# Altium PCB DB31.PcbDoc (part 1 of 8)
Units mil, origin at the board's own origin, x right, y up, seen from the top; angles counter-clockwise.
Board outline 3236.22 x 4456.69 mil, 8 copper layers (Top Layer, MidLayer1, MidLayer2, GND-Layer5, MidLayer3, VCC, MidLayer4, Bottom Layer), stack 61.8 mil thick; 226 components, 469 nets, 1815 pads, 1562 vias.
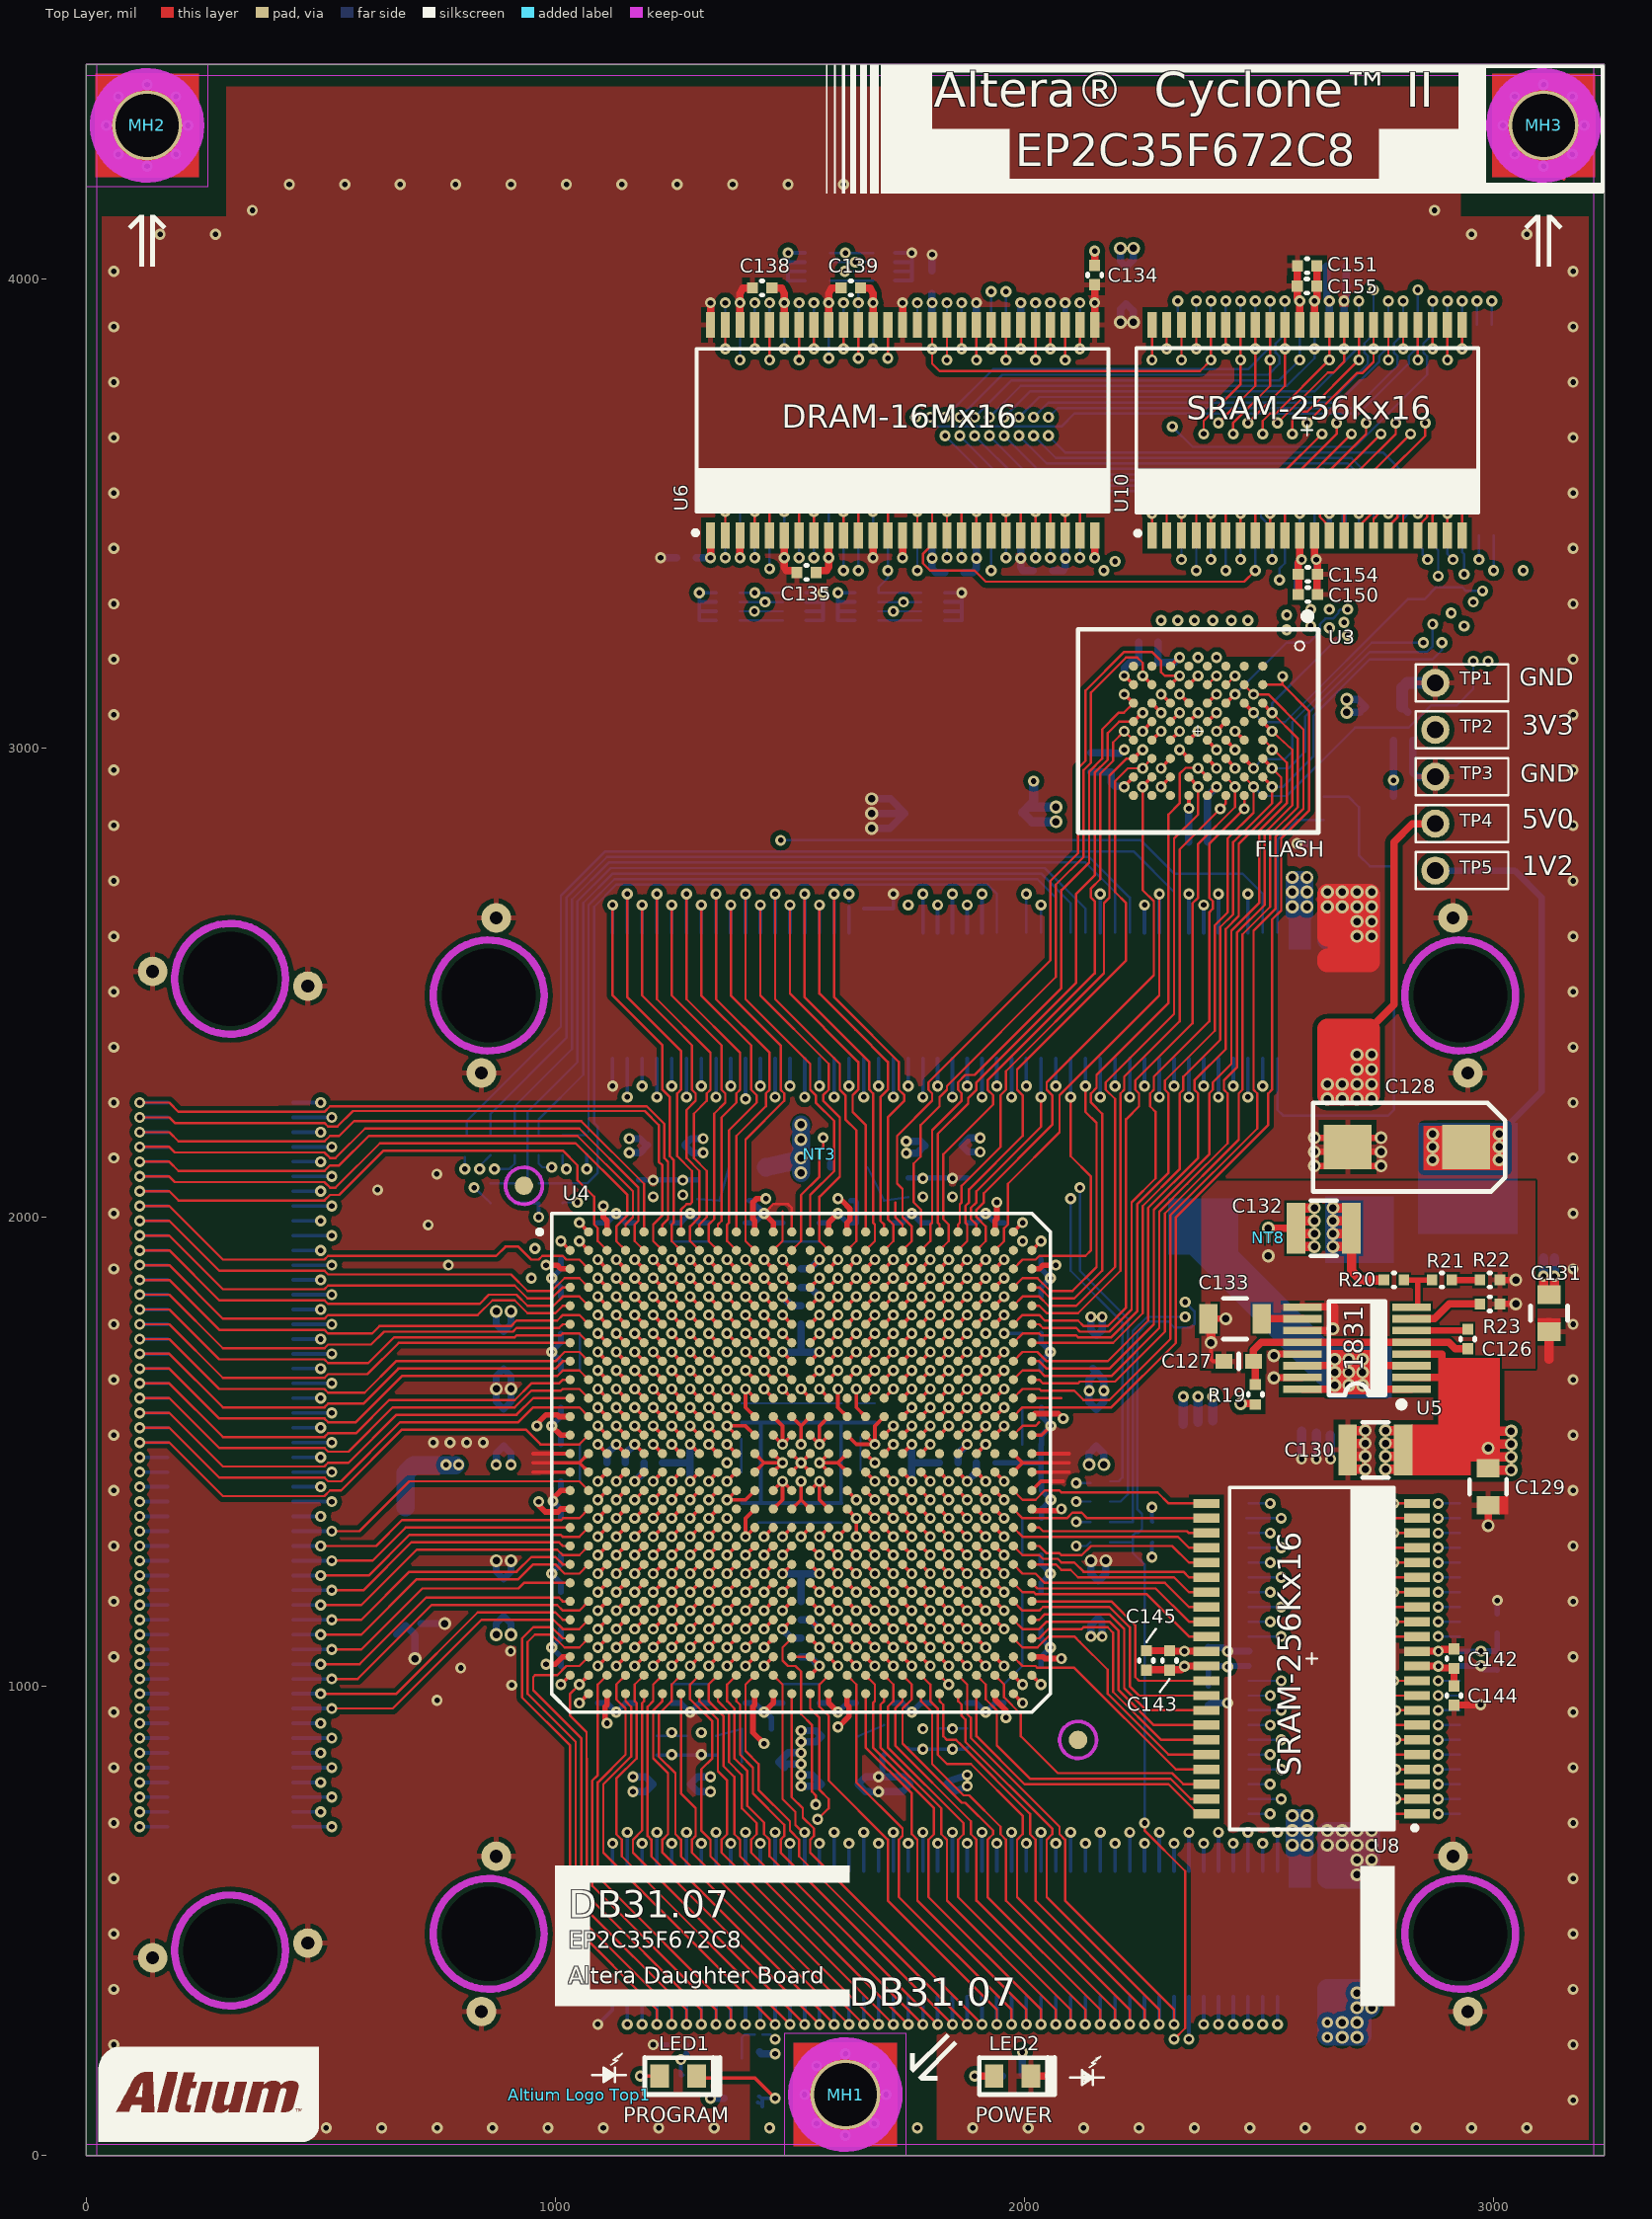
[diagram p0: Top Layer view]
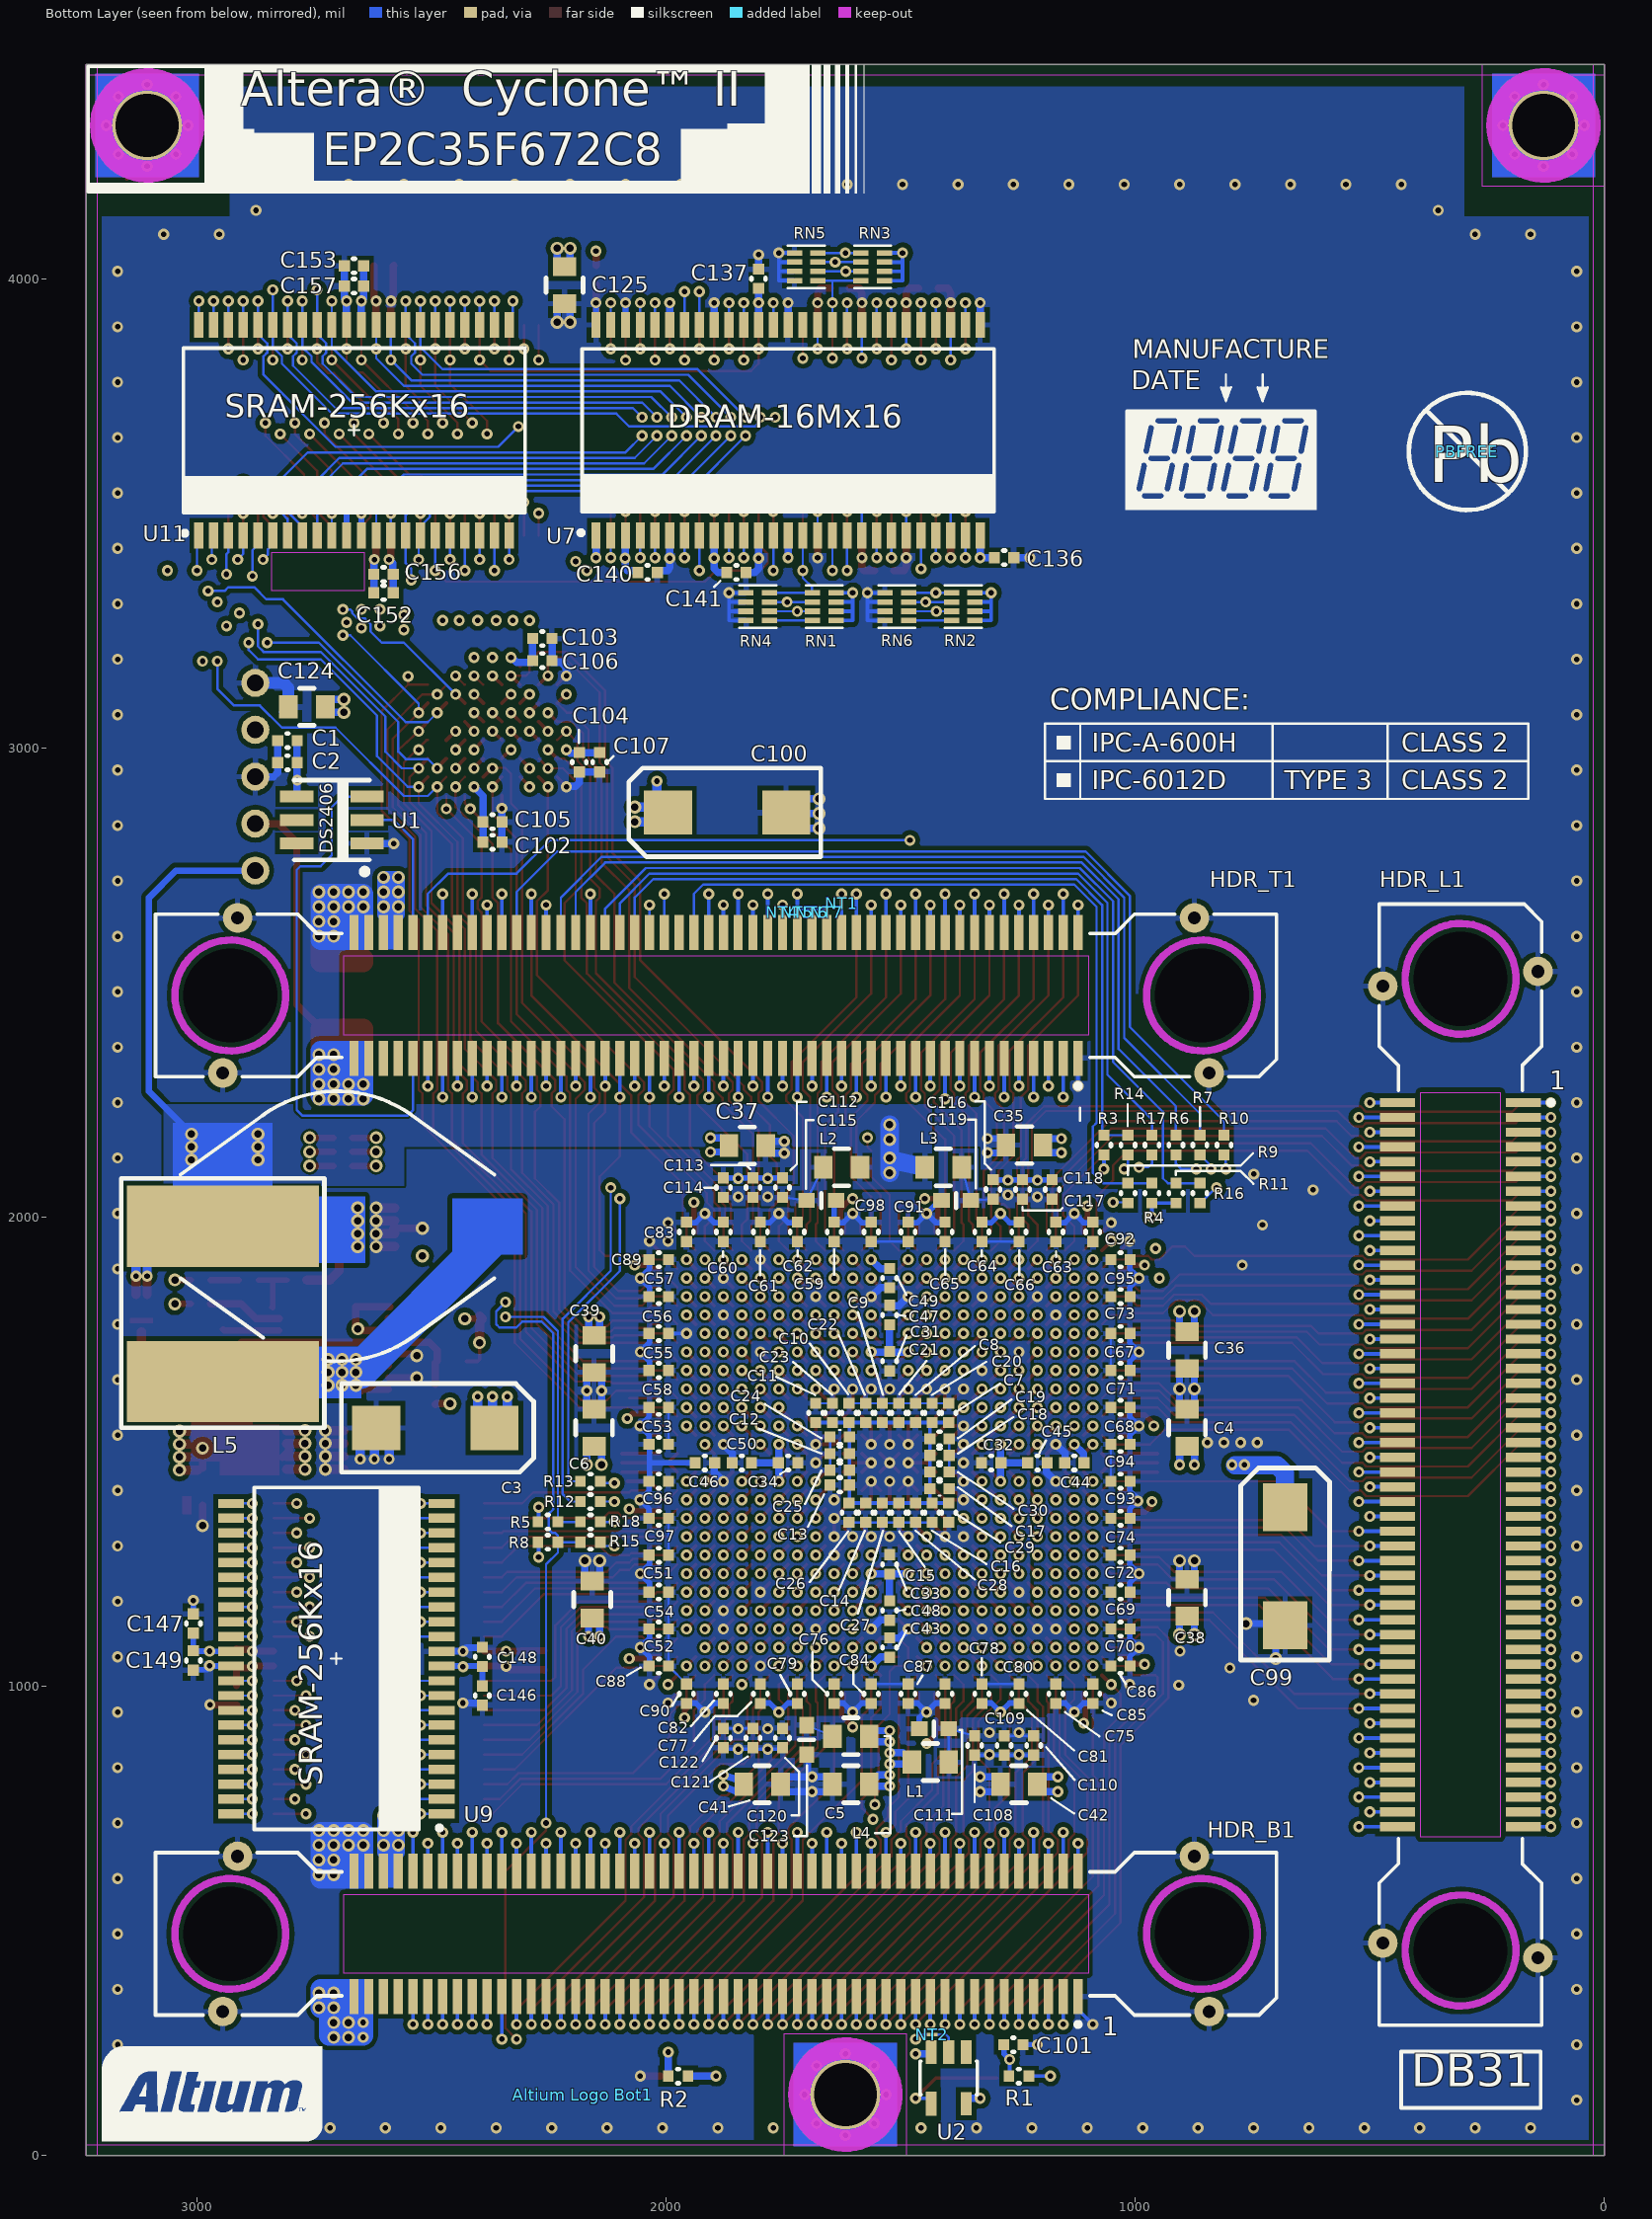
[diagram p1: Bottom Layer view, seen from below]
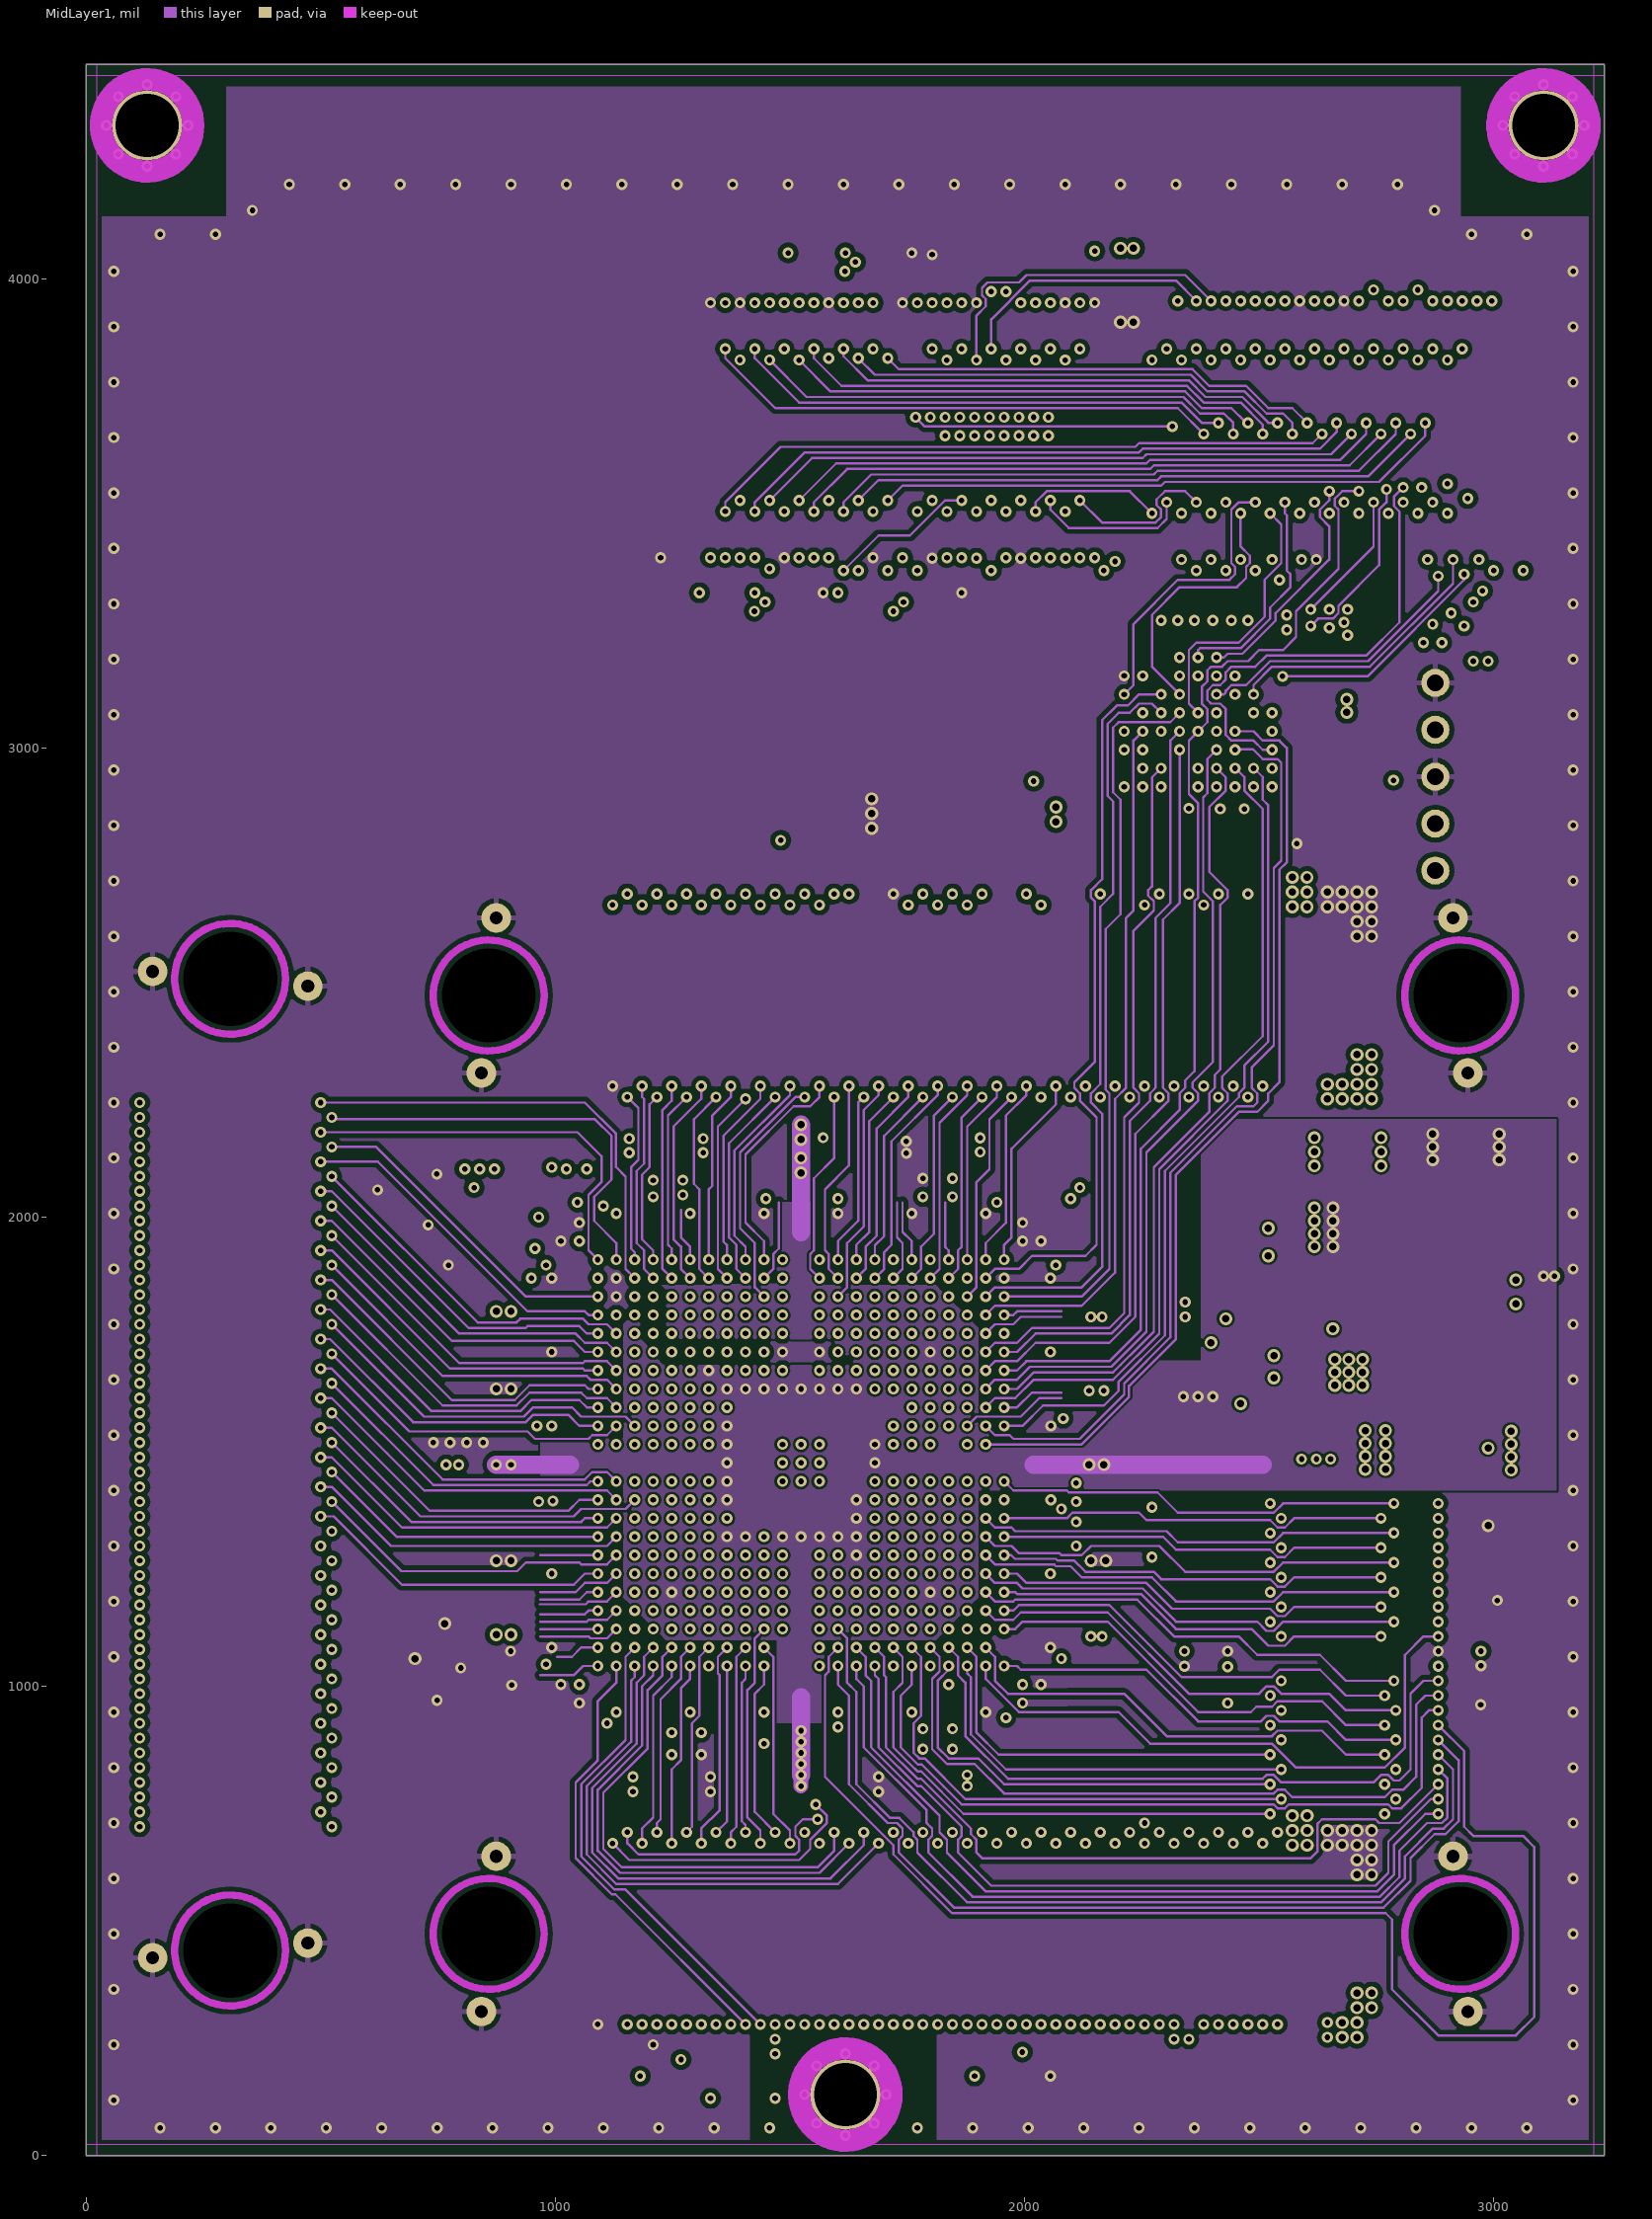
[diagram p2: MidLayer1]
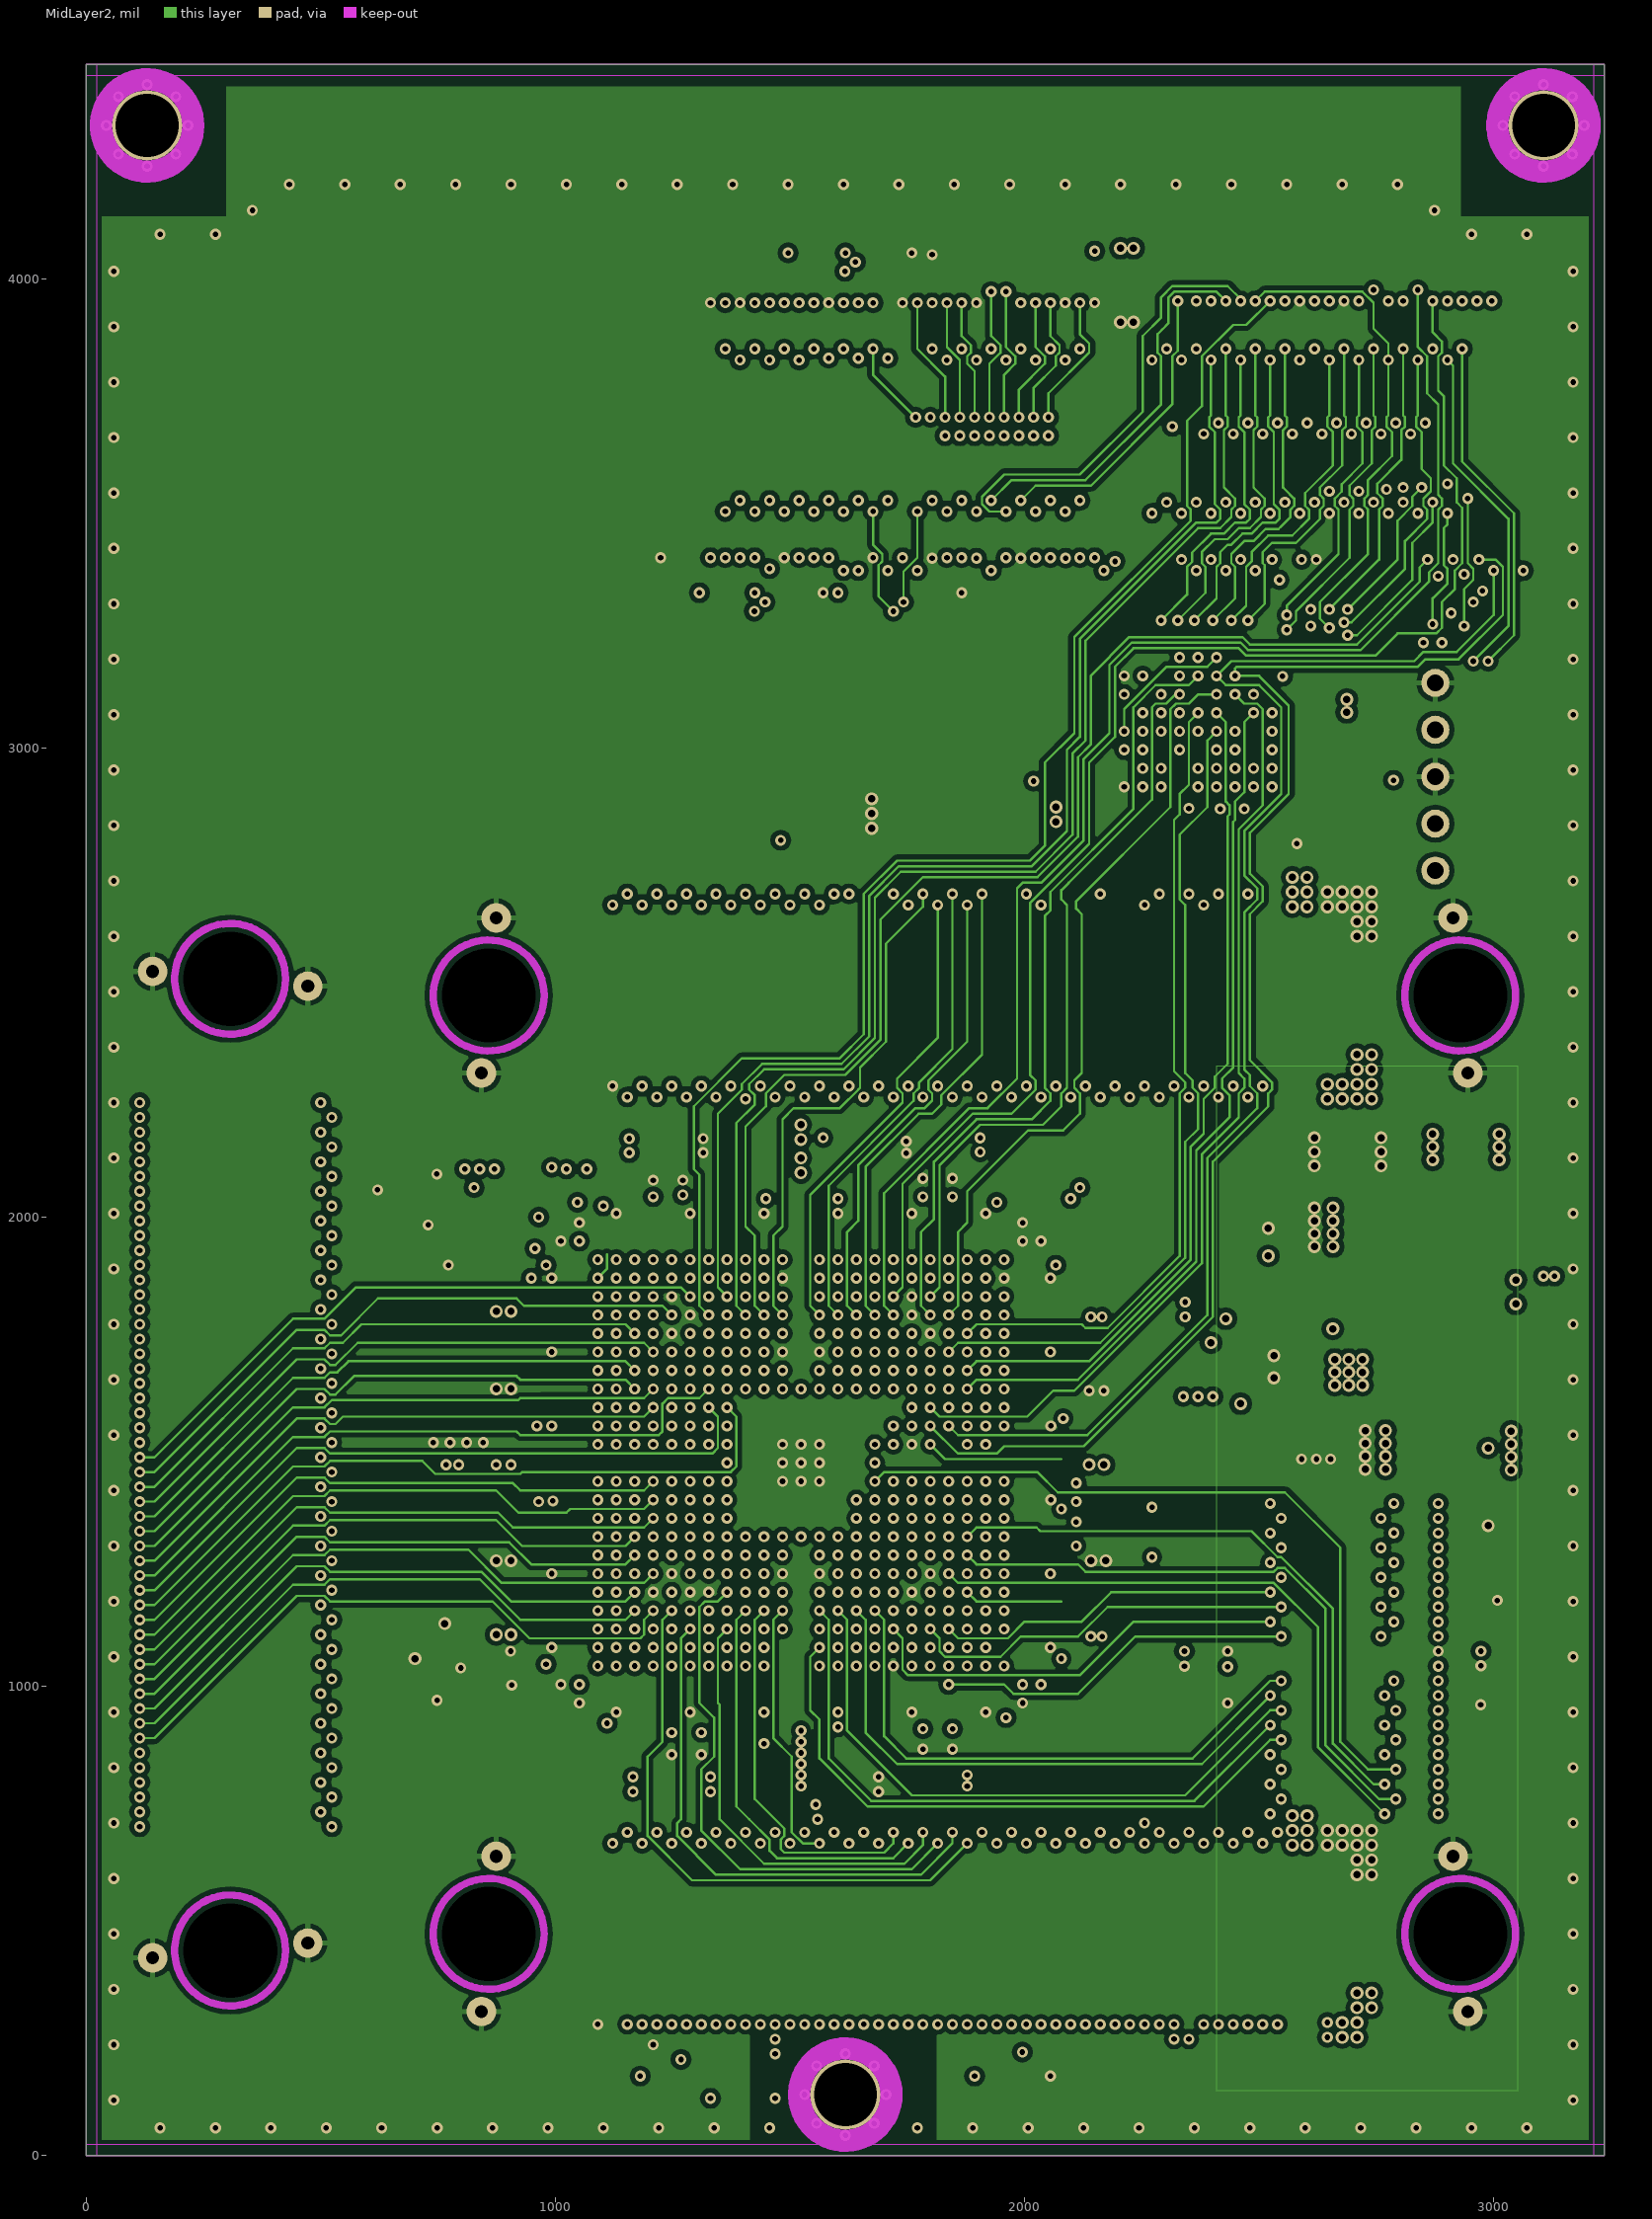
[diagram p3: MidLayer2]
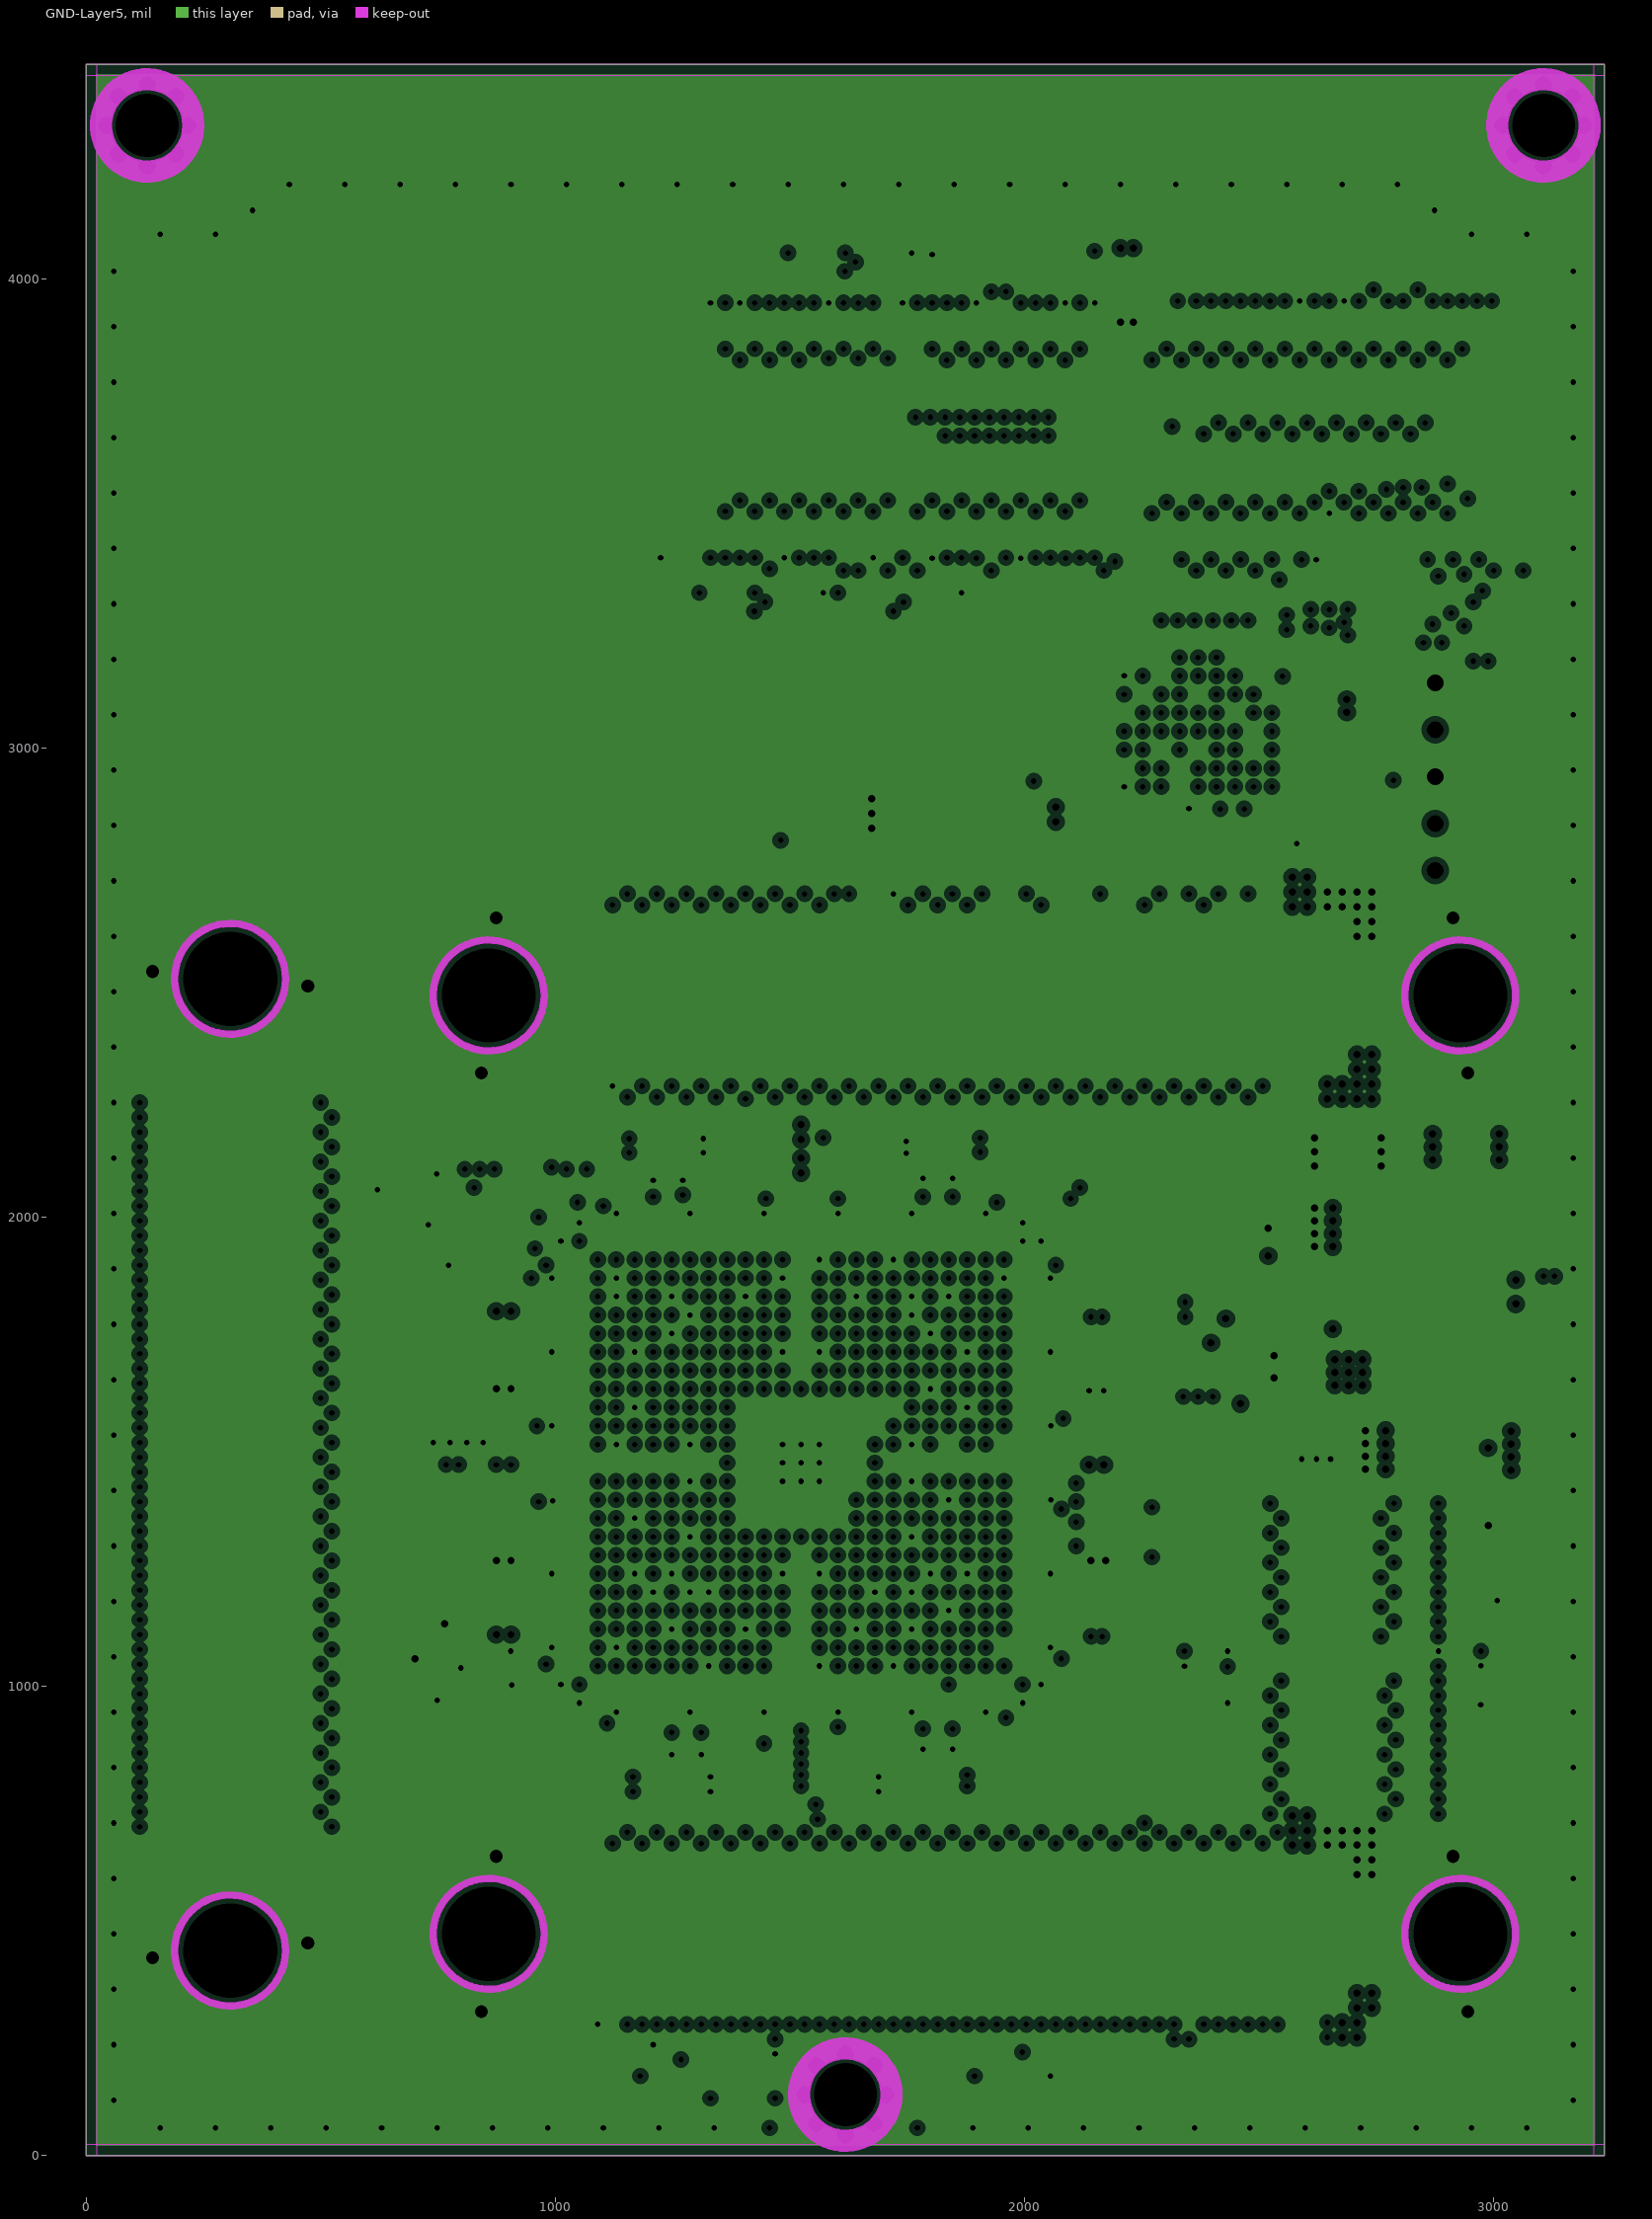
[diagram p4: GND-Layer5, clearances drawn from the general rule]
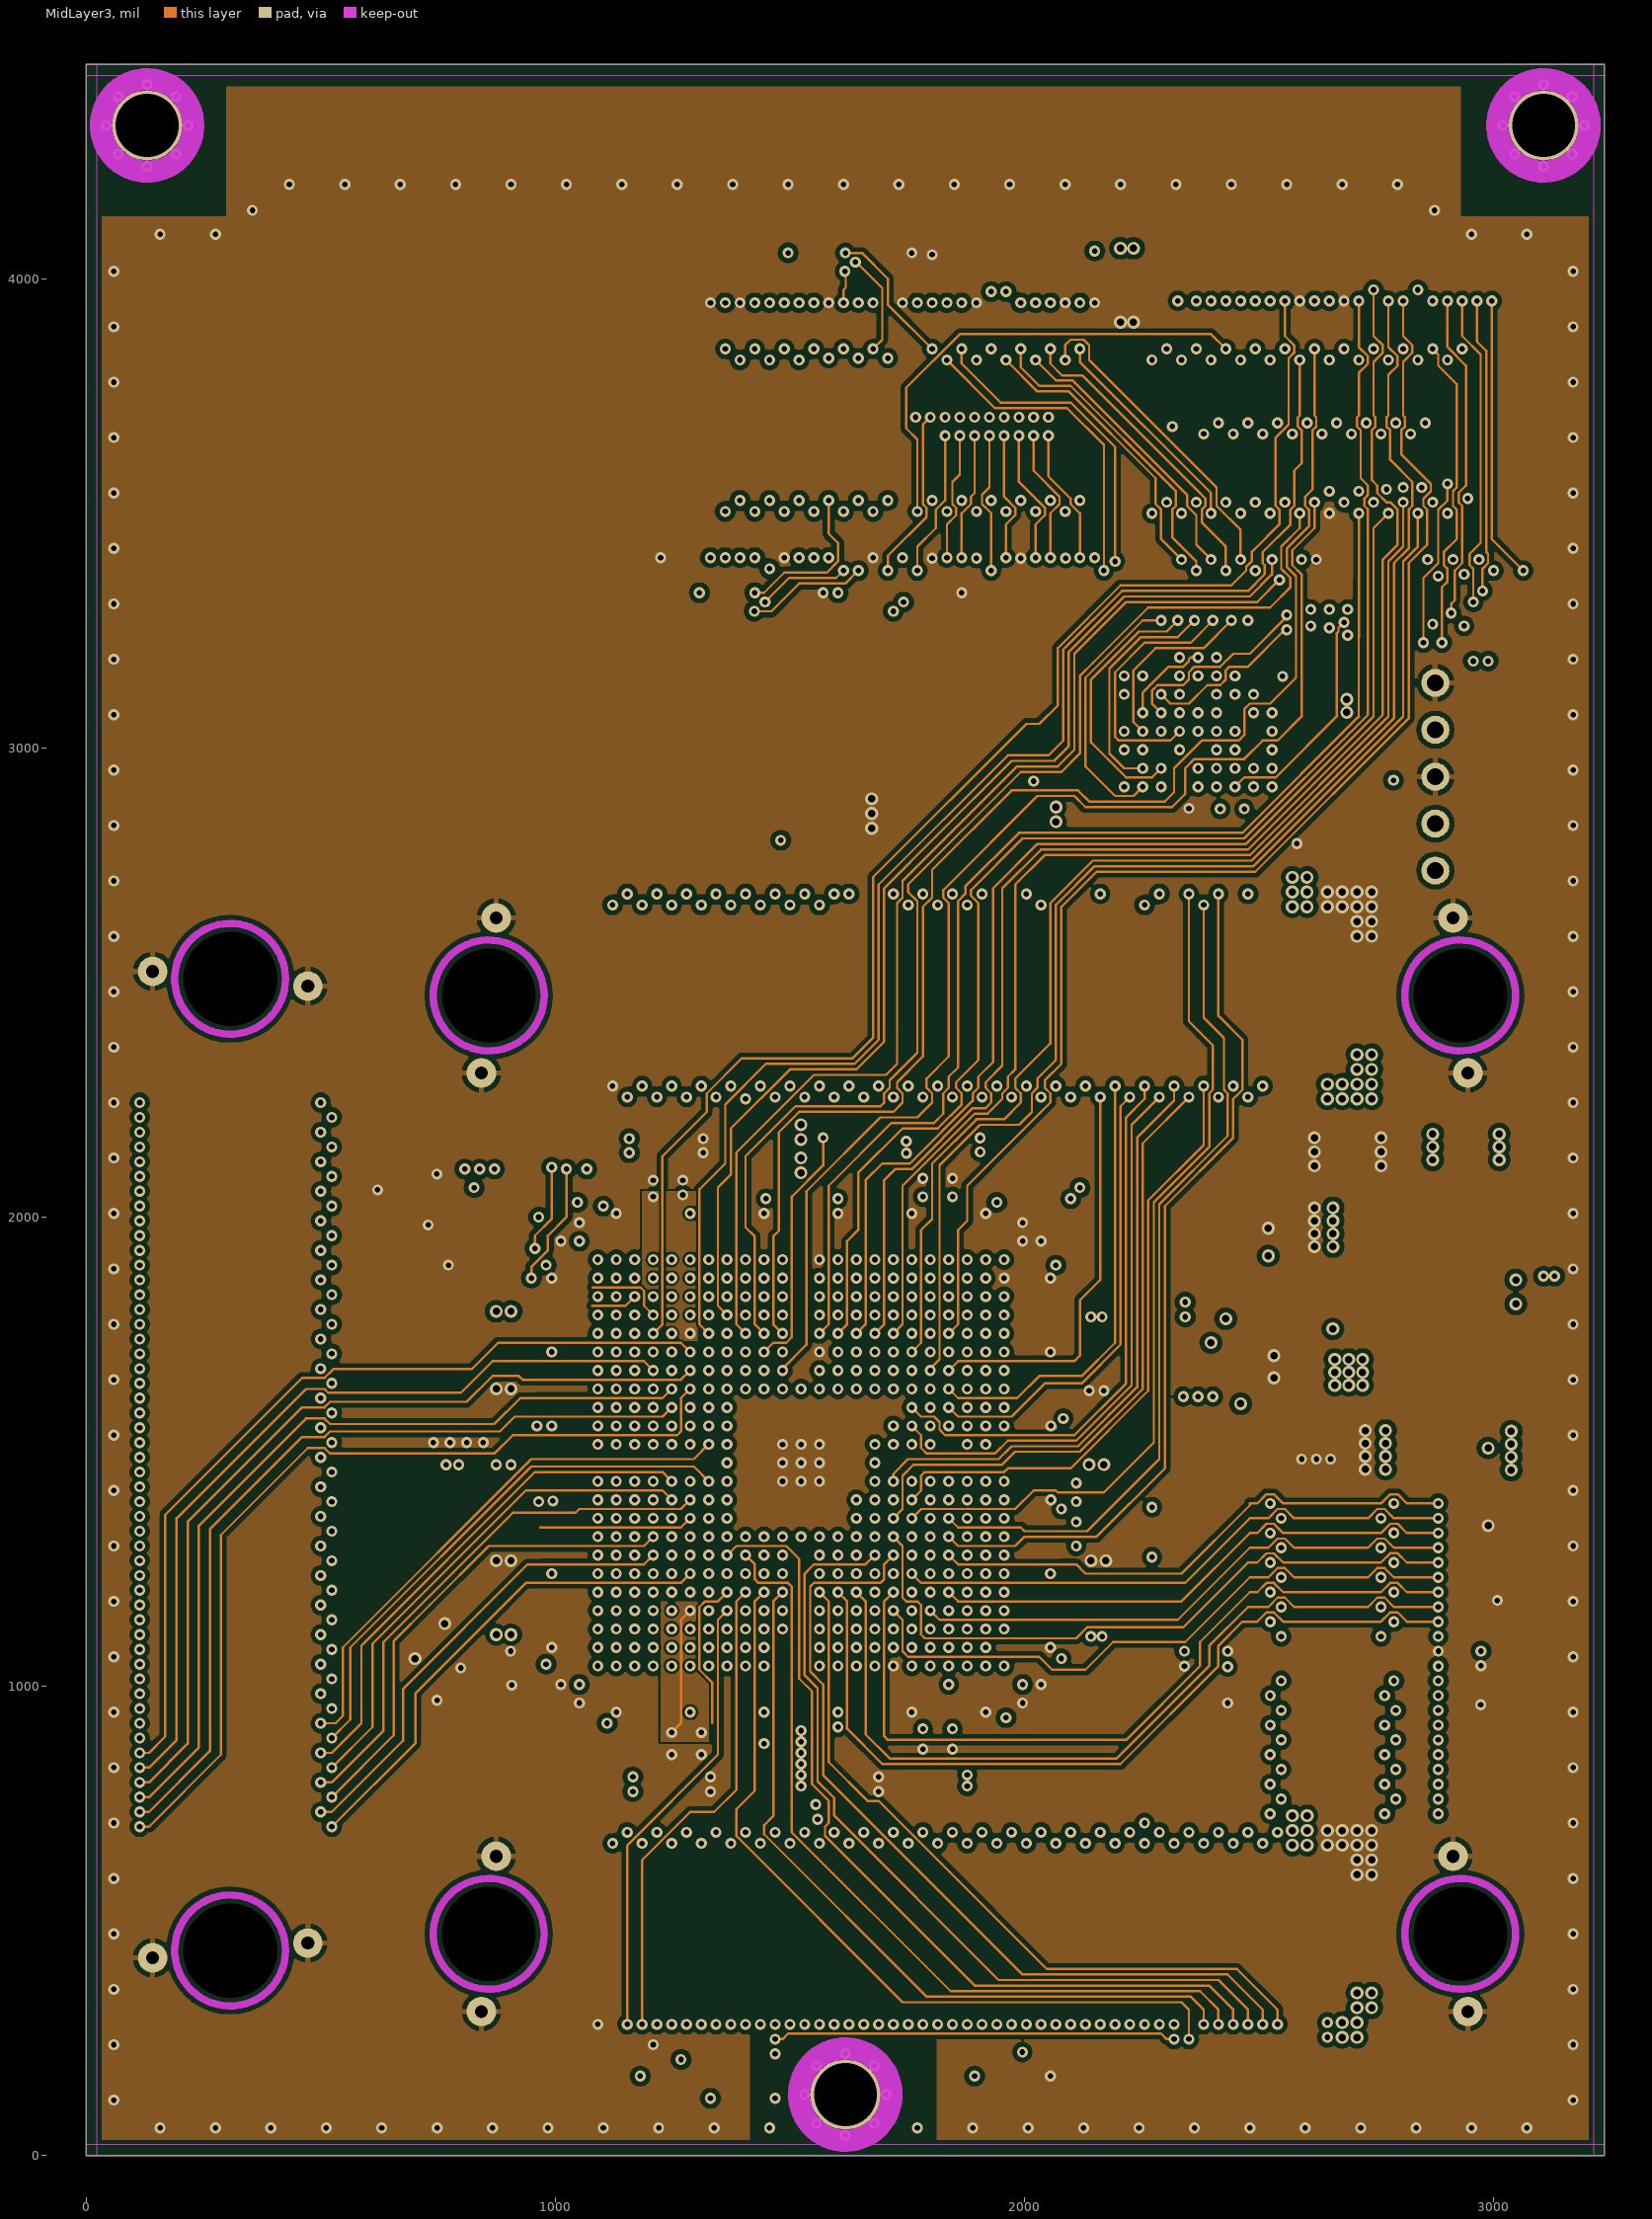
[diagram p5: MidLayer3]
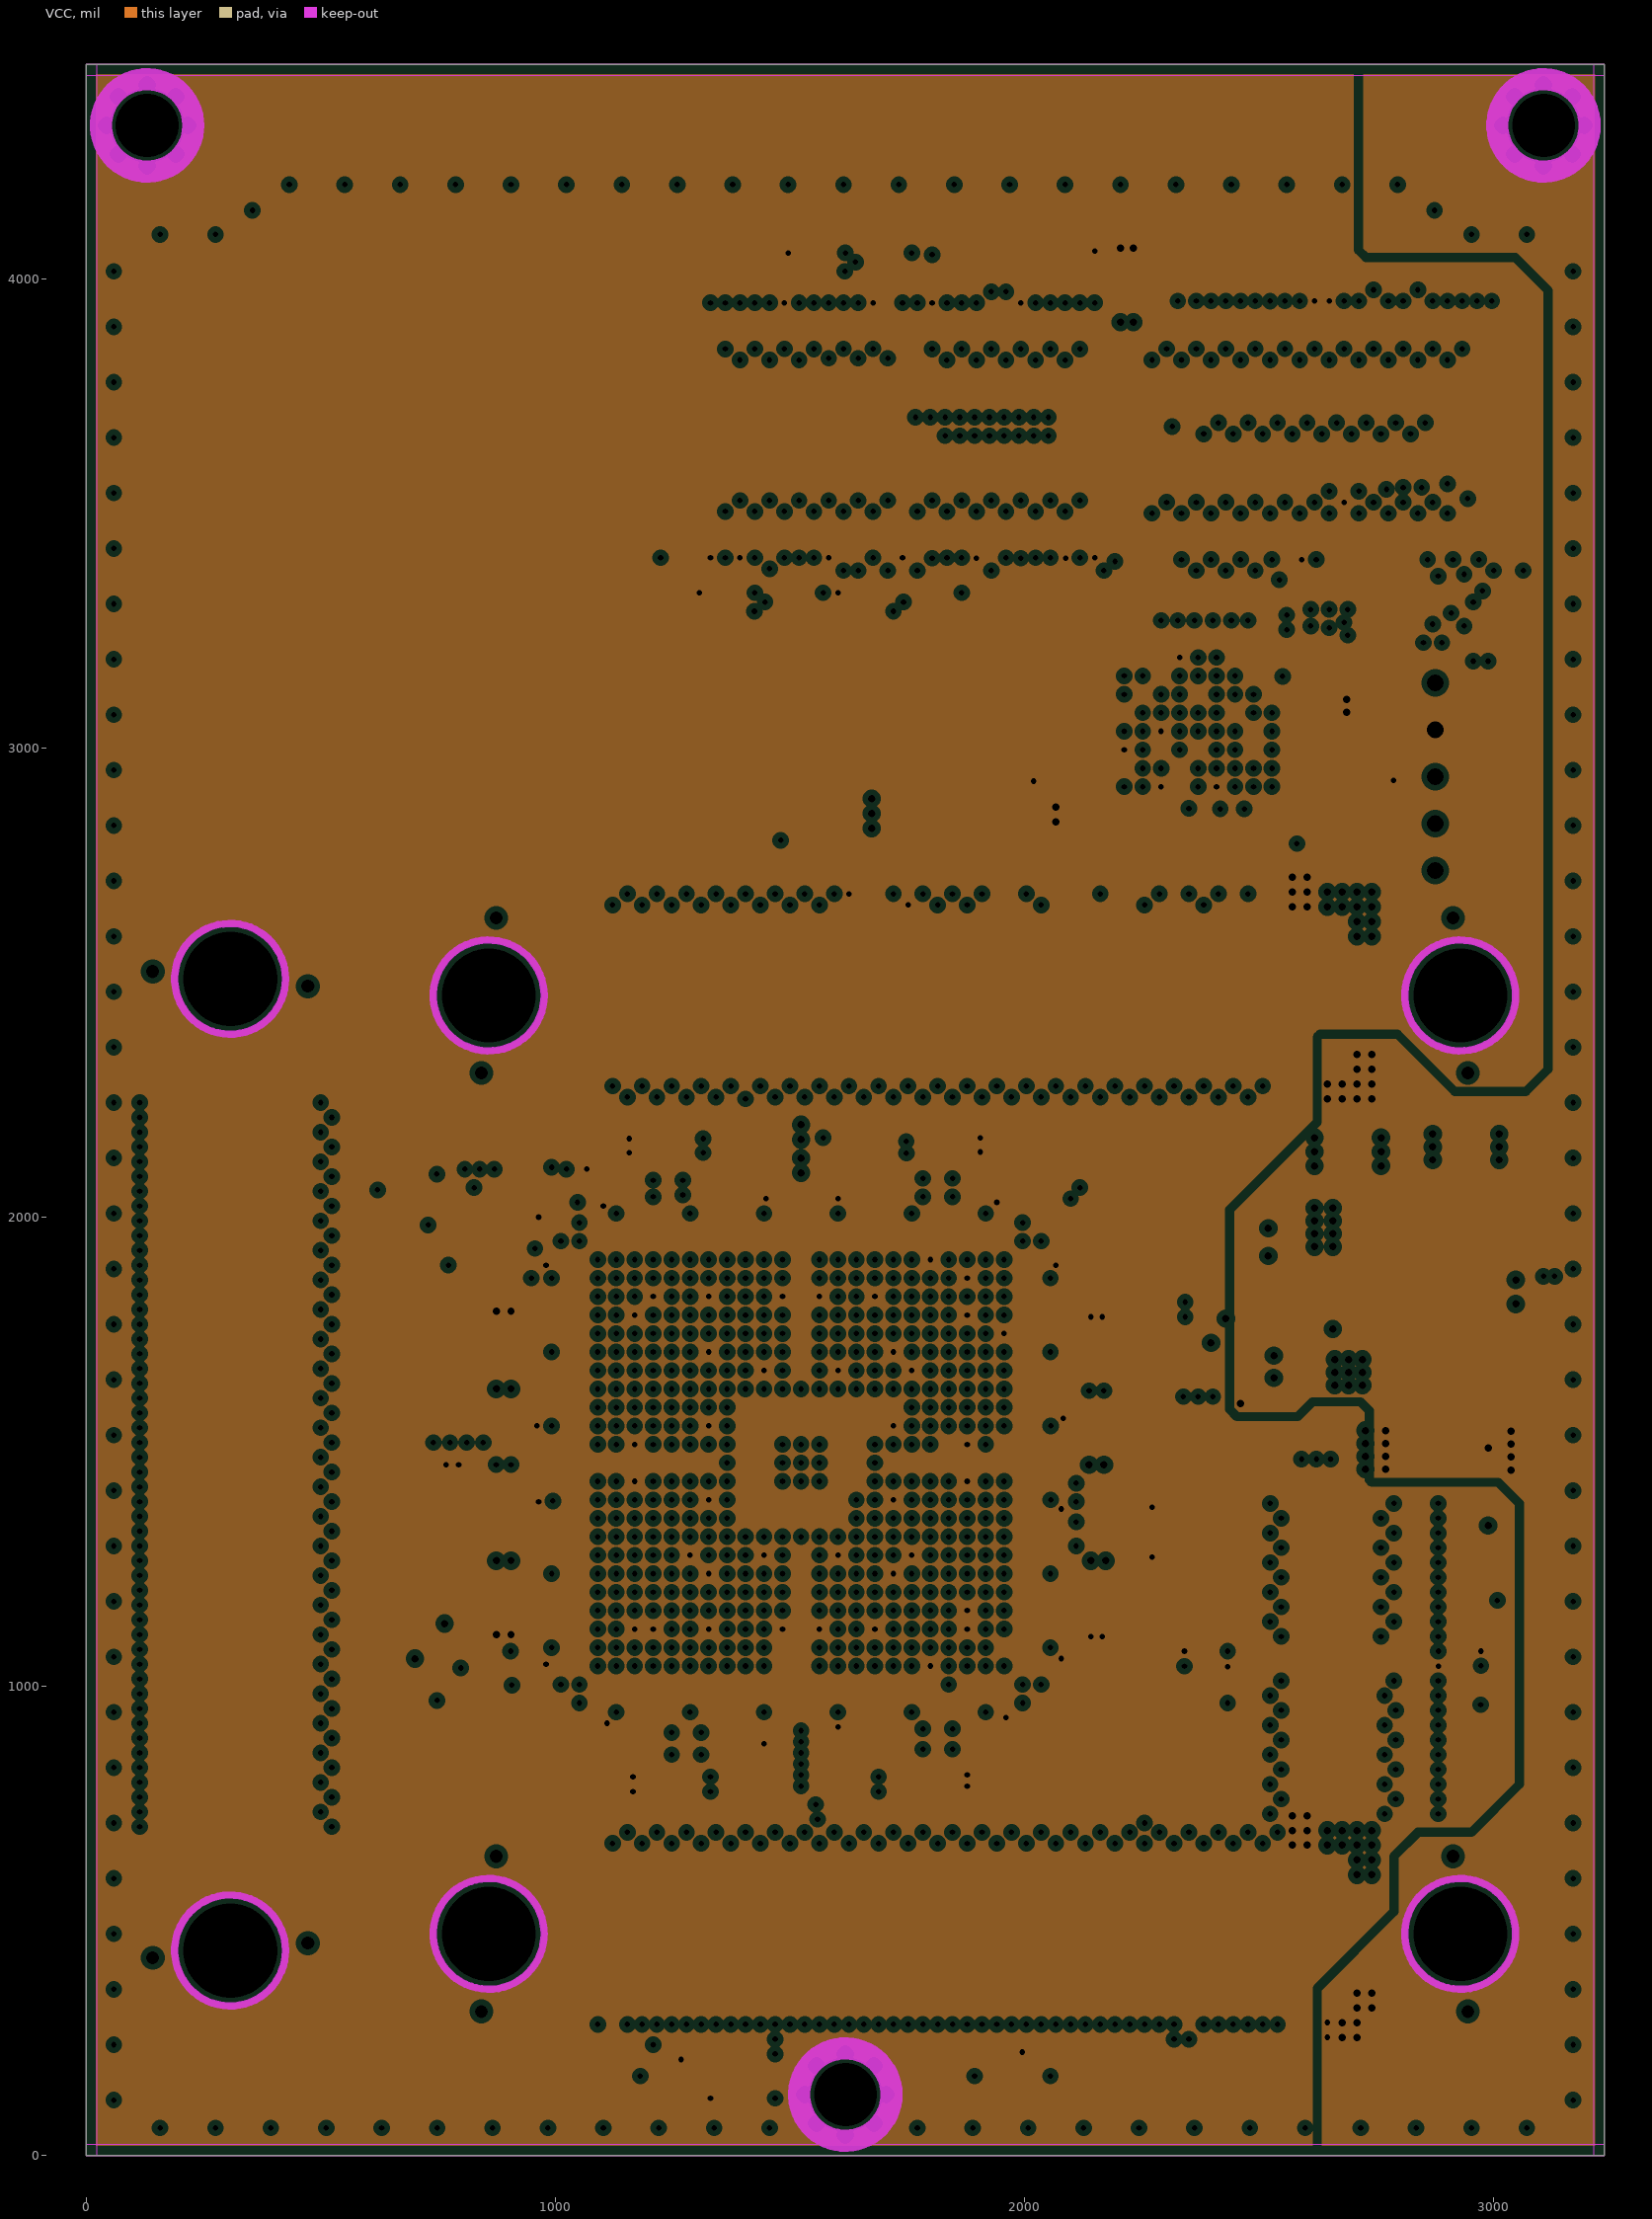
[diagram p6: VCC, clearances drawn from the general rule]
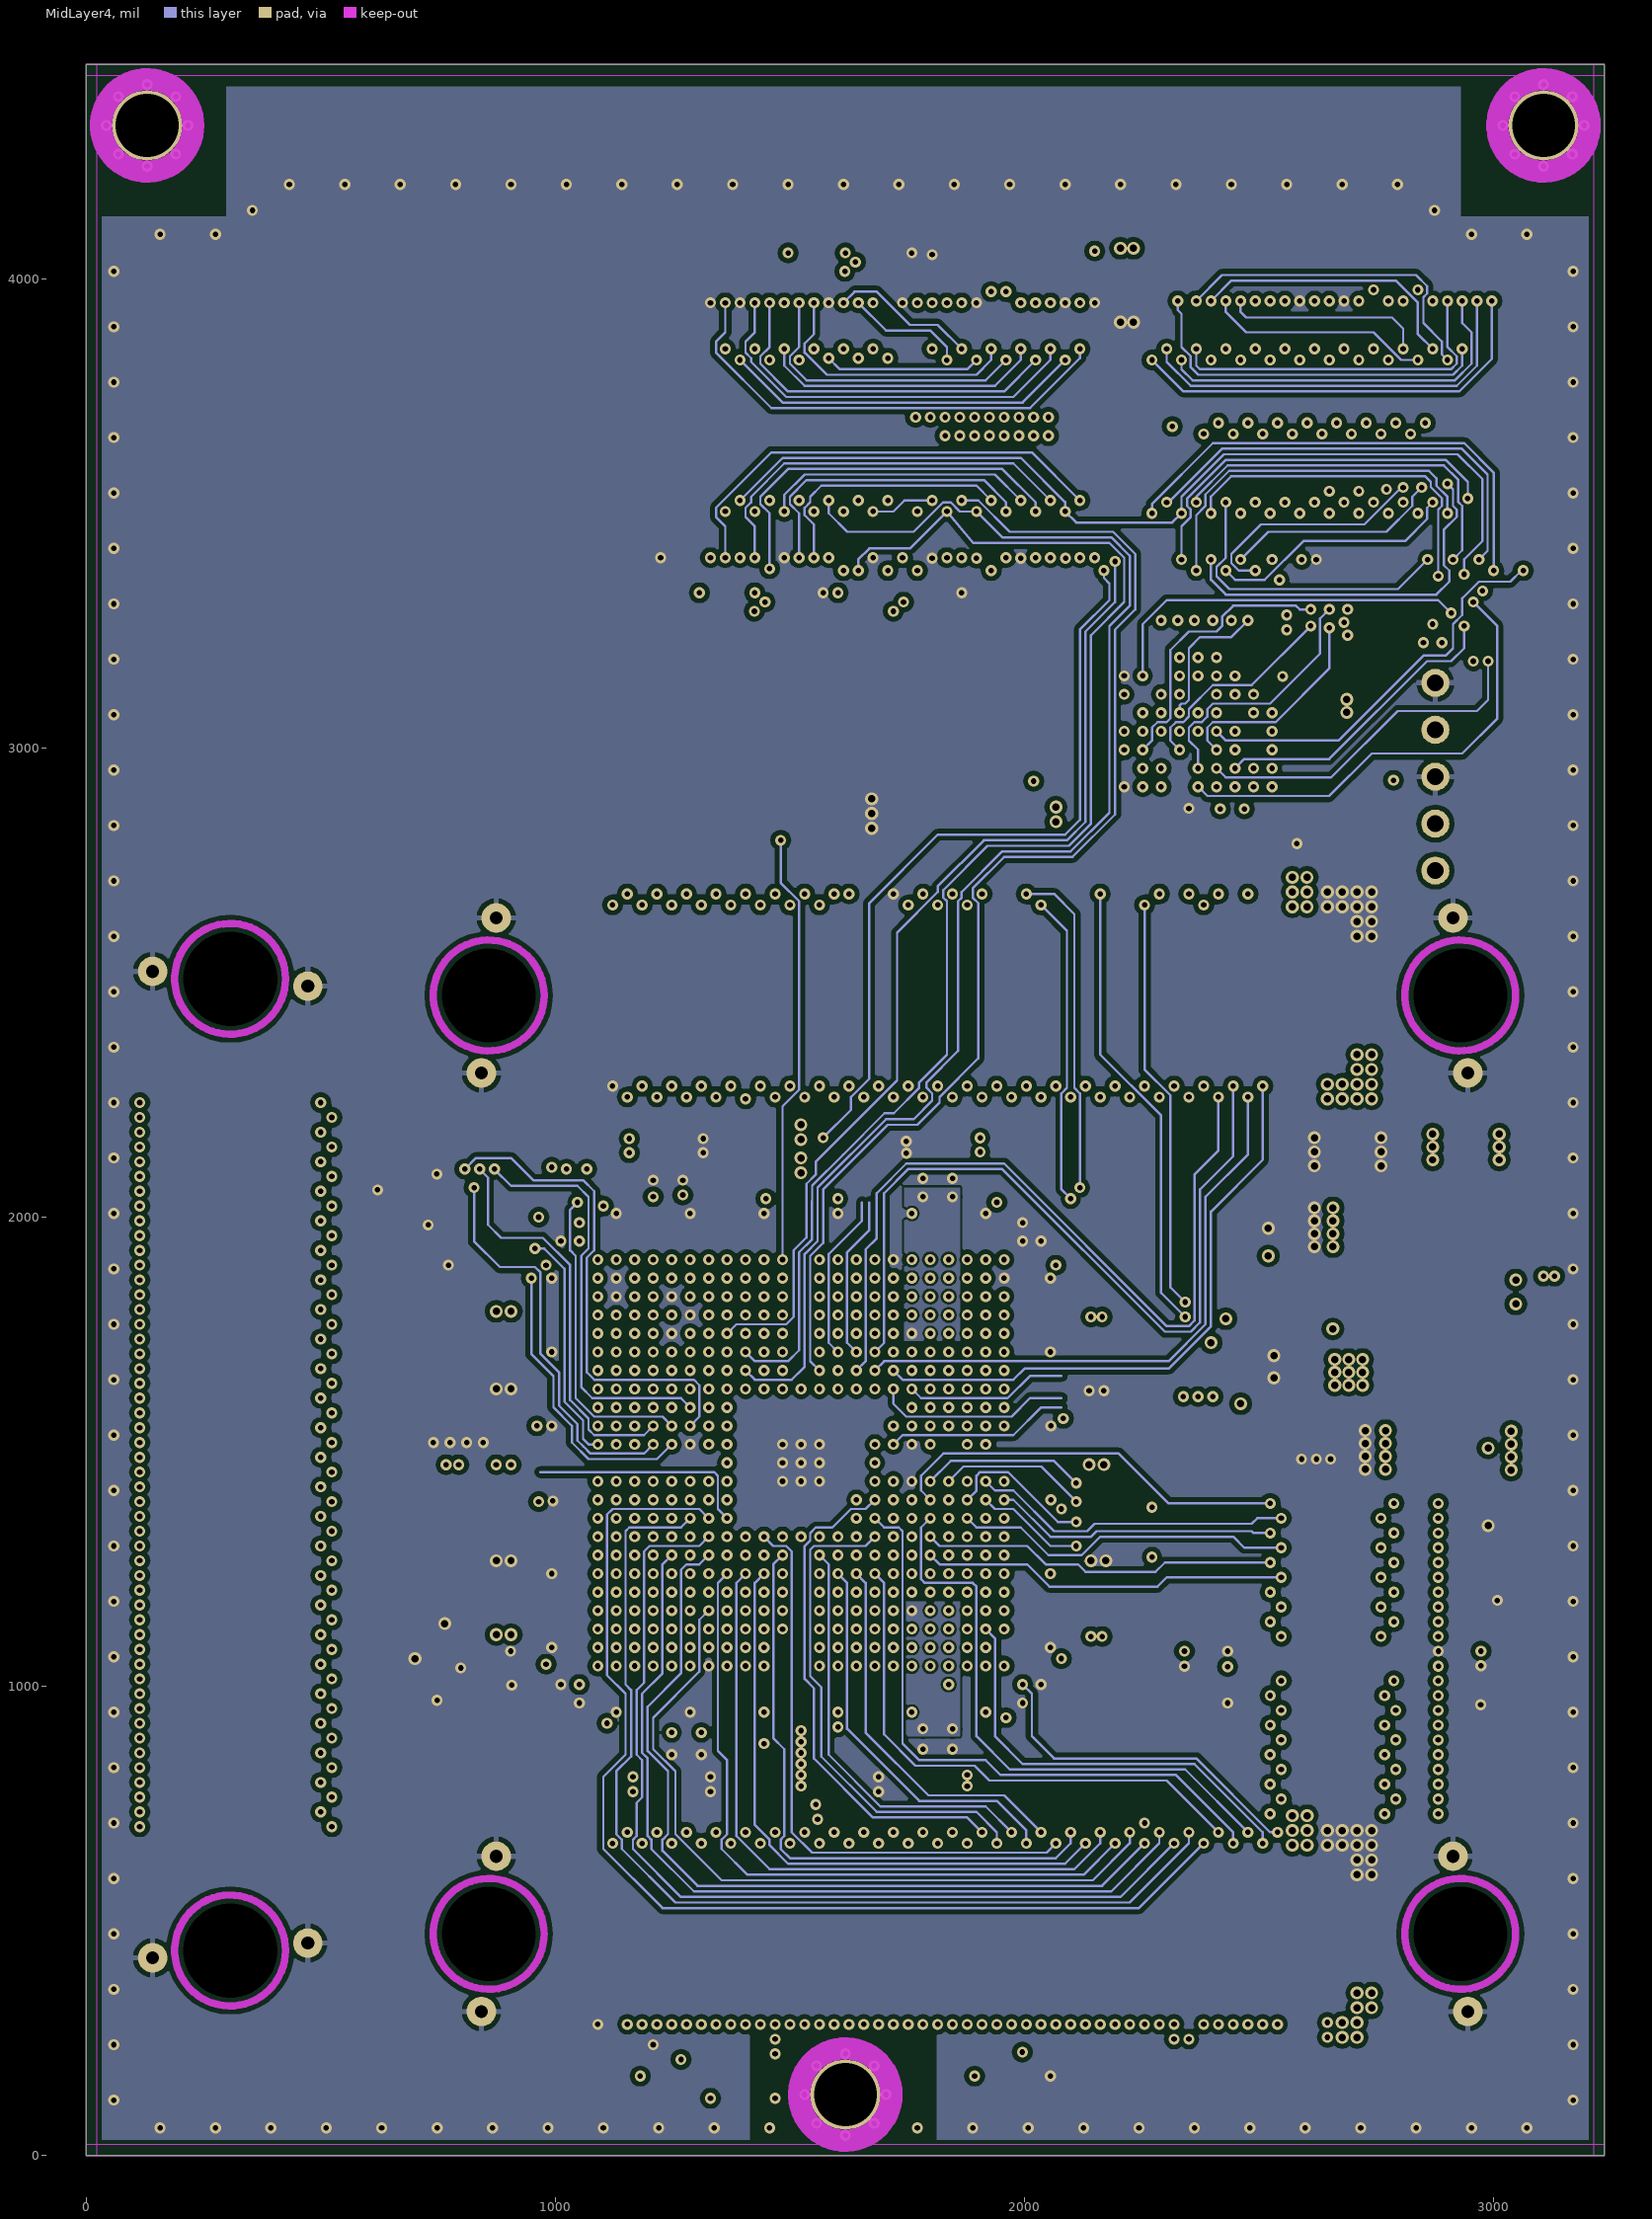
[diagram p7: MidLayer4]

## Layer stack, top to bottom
Top Layer: signal copper 1.7
Dielectric: prepreg 5, FR-4, Dk 4.2
MidLayer1: signal copper 1.4
Dielectric: core 10, FR-4, Dk 4.2
MidLayer2: signal copper 1.4
Dielectric: prepreg 5, FR-4, Dk 4.2
GND-Layer5: plane copper 1.4, net GND
Dielectric: core 10, FR-4, Dk 4.2
MidLayer3: signal copper 1.4
Dielectric: prepreg 5, FR-4, Dk 4.2
VCC: plane copper 1.4, net (Multiple Nets)
Dielectric: core 10, FR-4, Dk 4.2
MidLayer4: signal copper 1.4
Dielectric: prepreg 5, FR-4, Dk 4.2
Bottom Layer: signal copper 1.7

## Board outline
0,0 0,4456.69 1523.62,4456.69 3236.22,4456.69 3236.22,0

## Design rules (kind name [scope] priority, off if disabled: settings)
Clearance Clearance_Poly_Tight [InNamedPolygon('FPGAPWR-BL-GND') Or InNamedPolygon('FPGAPWR-BL-1V2') Or InNamedPolygon('FPGAPWR-BL-3V3') Or InNamedPolygon('FPGAPWR-ML1-1V2') Or InNamedPolygon('FPGAPWR-TL-1V2') Or InNamedPolygon('1V2-CONNECT-TO-L1-C17' ) Or InNamedPolygon('VCCA_PLL1_BL') Or InNamedPolygon('VCCA_PLL1_MID3') Or InNamedPolygon('VCCA_PLL2_BL') Or InNamedPolygon('VCCA_PLL2_MID4') Or InNamedPolygon('VCCA_PLL3_BL') Or InNamedPolygon('VCCA_PLL3_MID3') Or InNamedPolygon('VCCA_PLL4_BL') Or InNamedPolygon('VCCA_PLL4_MID4') Or InNamedPolygon('top-layer-1V2') Or InNamedPolygon('1V2-BL') Or InNamedPolygon('LX') Or InNamedPolygon('AGND-TOP')] p1: gap=5
Clearance Clearance_Polygon [InPolygon] p2: gap=10
Clearance "Pad-Pad Clearance" [IsPad vs IsPad] p3: gap=5
Clearance "Via-Pad Clearance" [IsVia vs IsPad] p4: gap=3.94
Clearance "General Clearance" [All] p5: gap=5
ComponentClearance [All] p1 off: gap=7.87 collisioncheckmode=3 verticalgap=10 showdistances=FALSE
DiffPairsRouting [All] p1: maxlimit=5 minlimit=5 mostfreqgap=5 maxuncoupledlength=200
FabricationTestPointUsage TestPointUsage [All] p1 off: valid=0 allowmultiple=FALSE
FabricationTestpoint Testpoint [All] p1 off: side=3 testpointundercomponent=TRUE minsize=40 maxsize=100 preferedsize=60 minholesize=0 maxholesize=40 preferedholesize=32 testpointgrid=1 allowsidetop=TRUE allowsidebottom=TRUE usegrid=TRUE gridtolerance=0.01
HoleSize [All] p1: absolutevalues=TRUE maxlimit=204.72 minlimit=7.87 maxpercent=80.000 minpercent=20.000
HoleToHoleClearance [All] p1: gap=4 allowstackedmicrovias=TRUE
MatchedLengths DiffPair_MatchedLengths [(IsDifferentialPair And (Name = 'DIFF_RX1'))] p1: tolerance=1000 checknetsindiffpair=TRUE checkdiffpairvsdiffpair=TRUE checkothers=TRUE
MinimumAnnularRing MinimumAnnularRing_NonPlated [(ObjectKind = 'Pad') And (HoleDiameter >= '0.7') And (PadIsPlated = 'False')] p1: minimumring=-196.85
MinimumAnnularRing [All] p2: minimumring=5.91
MinimumSolderMaskSliver [All] p1: minsoldermaskwidth=3
PlaneClearance [All] p1: clearance=11.81
PlaneConnect [All] p1: planeconnectstyle=Direct reliefexpansion=19.68 reliefentries=4 reliefconductorwidth=9.84 reliefairgap=9.84
PolygonConnect PolygonConnect_Via [IsVia] p1: connectstyle=Direct reliefconductorwidth=10 reliefentries=4 polygonreliefangle="90 Angle"
PolygonConnect "PolygonConnect - Heatsink" [(HasFootprint('TO-263') AND InNet('VCCINT'))] p2: connectstyle=Direct reliefconductorwidth=10 reliefentries=4 polygonreliefangle="90 Angle"
PolygonConnect [All] p3: connectstyle=Relief reliefconductorwidth=11.81 reliefentries=4 polygonreliefangle="90 Angle"
RoutingVias [All] p1: holewidth=11.81 width=23.62 viastyle="Through Hole" minholewidth=11.81 minwidth=23.62 maxholewidth=19.68 maxwidth=35.43
ShortCircuit ShortCircuit_1 [Net = 'No Net' vs Net = 'No Net'] p1: allowed=TRUE
ShortCircuit [All] p2: allowed=FALSE
SilkToSilkClearance SilkToSilkClearance_InvToFill [(ObjectKind = 'Text') And (TextKind <> 'Stroke Font') vs IsFill] p1: silktosilkclearance=0
SilkToSilkClearance SilkToSilkClearance_Labels [(ObjectKind = 'Text') And (TextKind <> 'Stroke Font') vs (ObjectKind = 'Text') And (TextKind <> 'Stroke Font')] p2: silktosilkclearance=0
SilkToSilkClearance SilkToSilkClearance_Pb [(ObjectKind = 'Text') And (StringText = 'Pb') vs istrack and onsilkscreen] p3: silktosilkclearance=0
SilkToSilkClearance [All] p4: silktosilkclearance=2
SilkscreenOverComponentPads [All] p1: minsilkscreentomaskgap=2
SolderMaskExpansion SolderMaskExpansion_Vias [IsVia] p1: expansion=-25.59
SolderMaskExpansion [All] p2: expansion=1.5
Width [All] p1: maxlimit=98.43 minlimit=5 preferedwidth=5
16 further rules are at their usual default settings.

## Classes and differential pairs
channel class SRAM_256Kx16_TSOP44: U_SRAM_K6R4016V1D-TC10T_256Kx161 U_SRAM_K6R4016V1D-TC10T_256Kx162
component class U_DB31_Hardware_Kit: PCB1
component class U_CommonMemory_Termination: RN1 RN2 RN3 RN4 RN5 RN6
net class PWRNET: 1V2 3V3 5V0 AGND GND
differential pair class DIFF_OUT: DIFF_TX0 DIFF_TX1 DIFF_TX2 DIFF_TX3
differential pair class DIFF_IN: DIFF_RX0 DIFF_RX1 DIFF_RX2 DIFF_RX3
net class SW[4..0]: SW0 SW1 SW2 SW3 SW4
net class LED[7..0]: LED0 LED1 LED2 LED3 LED4 LED5 LED6 LED7
net class IO[35..0]: IO0 IO1 IO2 IO3 IO4 IO5 IO6 IO7 IO8 IO9 IO10 IO11 IO12 IO13 IO14 IO15 IO16 IO17 IO18 IO19 IO20 IO21 IO22 IO23 IO24 IO25 IO26 IO27 IO28 IO29 IO30 IO31 IO32 IO33 IO34 IO35
net class FPGA_M[2..0]: FPGA_M0 FPGA_M1 FPGA_M2
net class FPGA_ID[3..0]: FPGA_ID0 FPGA_ID1 FPGA_ID2 FPGA_ID3
net class DIP[7..0]: DIP0 DIP1 DIP2 DIP3 DIP4 DIP5 DIP6 DIP7
net class BUS_NBE[3..0]: BUS_NBE0 BUS_NBE1 BUS_NBE2 BUS_NBE3
net class BUS_D[31..0]: BUS_D0 BUS_D1 BUS_D2 BUS_D3 BUS_D4 BUS_D5 BUS_D6 BUS_D7 BUS_D8 BUS_D9 BUS_D10 BUS_D11 BUS_D12 BUS_D13 BUS_D14 BUS_D15 BUS_D16 BUS_D17 BUS_D18 BUS_D19 BUS_D20 BUS_D21 BUS_D22 BUS_D23 BUS_D24 BUS_D25 BUS_D26 BUS_D27 BUS_D28 BUS_D29 BUS_D30 BUS_D31
component class U_MotherBoardConnectors: HDR_B1 HDR_L HDR_L1 HDR_T1 NT1
component class U_Bypass_1V2: C3 C4 C5 C6 C7 C8 C9 C10 C11 C12 C13 C14 C15 C16 C17 C18 C19 C20 C21 C22 C23 C24 C25 C26 C27 C28 C29 C30 C31 C32 C33 C34
component class U_Bypass_3V3: C35 C36 C37 C38 C39 C40 C41 C42 C43 C44 C45 C46 C47 C48 C49 C50 C51 C52 C53 C54 C55 C56 C57 C58 C59 C60 C61 C62 C63 C64 C65 C66 C67 C68 C69 C70 C71 C72 C73 C74 C75 C76 C77 C78 C79 C80 C81 C82 C83 C84 C85 C86 C87 C88 C89 C90 C91 C92 C93 C94 C95 C96 C97 C98 C102_FP C103_FP C104_FP C105_FP C106_FP
component class U_Bypass_Board: C1_PSU C4_MB C6_MB C99 C100
net class BUS_A[24..1]: BUS_A1 BUS_A2 BUS_A3 BUS_A4 BUS_A5 BUS_A6 BUS_A7 BUS_A8 BUS_A9 BUS_A10 BUS_A11 BUS_A12 BUS_A13 BUS_A14 BUS_A15 BUS_A16 BUS_A17 BUS_A18 BUS_A19 BUS_A20 BUS_A21 BUS_A22 BUS_A23 BUS_A24
net class DAU_TFT_BLUE[4..0]: DAU_TFT_BLUE0 DAU_TFT_BLUE1 DAU_TFT_BLUE2 DAU_TFT_BLUE3 DAU_TFT_BLUE4
net class DAU_TFT_CL[3..1]: DAU_TFT_CL1 DAU_TFT_CL2 DAU_TFT_CL3
net class DAU_TFT_GREEN[5..0]: DAU_TFT_GREEN0 DAU_TFT_GREEN1 DAU_TFT_GREEN2 DAU_TFT_GREEN3 DAU_TFT_GREEN4 DAU_TFT_GREEN5
net class DAU_TFT_RED[4..0]: DAU_TFT_RED0 DAU_TFT_RED1 DAU_TFT_RED2 DAU_TFT_RED3 DAU_TFT_RED4
net class EXTEND_A[49..0]: EXTEND_A0 EXTEND_A1 EXTEND_A2 EXTEND_A3 EXTEND_A4 EXTEND_A5 EXTEND_A6 EXTEND_A7 EXTEND_A8 EXTEND_A9 EXTEND_A10 EXTEND_A11 EXTEND_A12 EXTEND_A13 EXTEND_A14 EXTEND_A15 EXTEND_A16 EXTEND_A17 EXTEND_A18 EXTEND_A19 EXTEND_A20 EXTEND_A21 EXTEND_A22 EXTEND_A23 EXTEND_A24 EXTEND_A25 EXTEND_A26 EXTEND_A27 EXTEND_A28 EXTEND_A29 EXTEND_A30 EXTEND_A31 EXTEND_A32 EXTEND_A33 EXTEND_A34 EXTEND_A35 EXTEND_A36 EXTEND_A37 EXTEND_A38 EXTEND_A39 EXTEND_A40 EXTEND_A41 EXTEND_A42 EXTEND_A43 EXTEND_A44 EXTEND_A45 EXTEND_A46 EXTEND_A47 EXTEND_A48 EXTEND_A49
net class EXTEND_B[49..0]: EXTEND_B0 EXTEND_B1 EXTEND_B2 EXTEND_B3 EXTEND_B4 EXTEND_B5 EXTEND_B6 EXTEND_B7 EXTEND_B8 EXTEND_B9 EXTEND_B10 EXTEND_B11 EXTEND_B12 EXTEND_B13 EXTEND_B14 EXTEND_B15 EXTEND_B16 EXTEND_B17 EXTEND_B18 EXTEND_B19 EXTEND_B20 EXTEND_B21 EXTEND_B22 EXTEND_B23 EXTEND_B24 EXTEND_B25 EXTEND_B26 EXTEND_B27 EXTEND_B28 EXTEND_B29 EXTEND_B30 EXTEND_B31 EXTEND_B32 EXTEND_B33 EXTEND_B34 EXTEND_B35 EXTEND_B36 EXTEND_B37 EXTEND_B38 EXTEND_B39 EXTEND_B40 EXTEND_B41 EXTEND_B42 EXTEND_B43 EXTEND_B44 EXTEND_B45 EXTEND_B46 EXTEND_B47 EXTEND_B48 EXTEND_B49
net class EXTEND_C[49..0]: EXTEND_C0 EXTEND_C1 EXTEND_C2 EXTEND_C3 EXTEND_C4 EXTEND_C5 EXTEND_C6 EXTEND_C7 EXTEND_C8 EXTEND_C9 EXTEND_C10 EXTEND_C11 EXTEND_C12 EXTEND_C13 EXTEND_C14 EXTEND_C15 EXTEND_C16 EXTEND_C17 EXTEND_C18 EXTEND_C19 EXTEND_C20 EXTEND_C21 EXTEND_C22 EXTEND_C23 EXTEND_C24 EXTEND_C25 EXTEND_C26 EXTEND_C27 EXTEND_C28 EXTEND_C29 EXTEND_C30 EXTEND_C31 EXTEND_C32 EXTEND_C33 EXTEND_C34 EXTEND_C35 EXTEND_C36 EXTEND_C37 EXTEND_C38 EXTEND_C39 EXTEND_C40 EXTEND_C41 EXTEND_C42 EXTEND_C43 EXTEND_C44 EXTEND_C45 EXTEND_C46 EXTEND_C47 EXTEND_C48 EXTEND_C49
component class U_PSU: C124 C125 NT8 TP1 TP2 TP3 TP4 TP5
net class SRAM1_A[18..0]: SRAM1_A0 SRAM1_A1 SRAM1_A2 SRAM1_A3 SRAM1_A4 SRAM1_A5 SRAM1_A6 SRAM1_A7 SRAM1_A8 SRAM1_A9 SRAM1_A10 SRAM1_A11 SRAM1_A12 SRAM1_A13 SRAM1_A14 SRAM1_A15 SRAM1_A16 SRAM1_A17 SRAM1_A18
net class SRAM1_D[15..0]: SRAM1_D0 SRAM1_D1 SRAM1_D2 SRAM1_D3 SRAM1_D4 SRAM1_D5 SRAM1_D6 SRAM1_D7 SRAM1_D8 SRAM1_D9 SRAM1_D10 SRAM1_D11 SRAM1_D12 SRAM1_D13 SRAM1_D14 SRAM1_D15
net class SRAM2_A[18..0]: SRAM2_A0 SRAM2_A1 SRAM2_A2 SRAM2_A3 SRAM2_A4 SRAM2_A5 SRAM2_A6 SRAM2_A7 SRAM2_A8 SRAM2_A9 SRAM2_A10 SRAM2_A11 SRAM2_A12 SRAM2_A13 SRAM2_A14 SRAM2_A15 SRAM2_A16 SRAM2_A17 SRAM2_A18
net class SRAM2_D[15..0]: SRAM2_D0 SRAM2_D1 SRAM2_D2 SRAM2_D3 SRAM2_D4 SRAM2_D5 SRAM2_D6 SRAM2_D7 SRAM2_D8 SRAM2_D9 SRAM2_D10 SRAM2_D11 SRAM2_D12 SRAM2_D13 SRAM2_D14 SRAM2_D15
component class U_1WB_DS2406_EPROM: C1 C2 U1
component class U_FPGA: D1 F1 J1_U NT2 NT3 NT4 NT5 NT6 NT7 NT8 R1HD R2HD R3 R3HD R4 R4HD R5 R6 R7 R8 R9 R10 R11 R12 R13 R14 R15 R16 R17 R18 R20 R25 R26 R27 U4
component class U_FPGA_Power: C108 C109 C110 C111 C112 C113 C114 C115 C116 C117 C118 C119 C120 C121 C122 C123 L1 L2 L3 L4
net class FPGACONF: CONF_DONE DATA0 DCLK FPGA_CCLK FPGA_DIN FPGA_DONE FPGA_INIT FPGA_M0 FPGA_M1 FPGA_PROGRAM FPGA_TCK FPGA_TDI FPGA_TDO FPGA_TMS MSEL0 MSEL1 NCONFIG NSTATUS TCK TDI TDO TMS
net class PLL: VCCA_PLL1 VCCA_PLL2 VCCA_PLL3 VCCA_PLL4
component class U_MOUNTS: "Altium Logo Bot1" "Altium Logo Top1" LB1 MH1 MH2 MH3
component class COM_FLASH: C102 C103 C104 C105 C106 C107 U3
component class U_DaughterBoard_LEDS: C101 LED1 LED2 R1 R2 U2
component class U_SRAM_K6R4016V1D-TC10T_256Kx161: C142 C143 C144 C145 U8
component class U_SRAM_K6R4016V1D-TC10T_256Kx162: C1_SM C2_SM C4_SM C146 C147 C148 C149 U1_SM U9
component class U_PSU_MAX1831_1V2_ALT: C126 C127 C128 C129 C130 C131 C132 C133 L5 R19 R20 R21 R22 R23 TP7 TP8 U5
component class COM_SDRAM: C134 C135 C136 C137 C138 C139 C140 C141 U6 U7
component class COM_SRAM: C150 C151 C152 C153 C154 C155 C156 C157 U10 U11

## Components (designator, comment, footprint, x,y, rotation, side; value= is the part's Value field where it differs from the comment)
"Altium Logo Bot1" "Altium" Logo-Altium 2177.17,129.92 r180 bottom
"Altium Logo Top1" "Altium" Logo-Altium 1051.18,129.92 r0 top
C1 "0.1uF 16V" CAPC1005-STAR 2807.08,3015.74 r180 bottom
C2 "10nF 16V" CAPC1005-STAR 2807.08,2968.5 r0 bottom
C3 "220uF 10V" CAPC7343-STAR 2492.13,1551.18 r0 bottom (schematic designator C5_MB)
C4 "10uF 10V" CAPC2012-STAR 889.76,1551.18 r90 bottom (schematic designator C1_FP)
C5 "10uF 10V" CAPC2012-STAR 1606.3,791.34 r0 bottom (schematic designator C2_FP)
C6 "10uF 10V" CAPC2012-STAR 2153.54,1551.18 r90 bottom (schematic designator C3_FP)
C7 "0.1uF 16V" CAPC1005-STAR 1397.64,1582.67 r270 bottom (schematic designator C4_FP)
C8 "0.1uF 16V" CAPC1005-STAR 1468.5,1582.67 r270 bottom (schematic designator C5_FP)
C9 "0.1uF 16V" CAPC1005-STAR 1539.37,1582.67 r270 bottom (schematic designator C6_FP)
C10 "0.1uF 16V" CAPC1005-STAR 1610.23,1582.67 r270 bottom (schematic designator C7_FP)
C11 "0.1uF 16V" CAPC1005-STAR 1681.1,1582.67 r270 bottom (schematic designator C8_FP)
C12 "0.1uF 16V" CAPC1005-STAR 1629.92,1496.06 r180 bottom (schematic designator C9_FP)
C13 "0.1uF 16V" CAPC1005-STAR 1629.92,1429.13 r180 bottom (schematic designator C10_FP)
C14 "0.1uF 16V" CAPC1005-STAR 1574.8,1370.08 r90 bottom (schematic designator C11_FP)
C15 "0.1uF 16V" CAPC1005-STAR 1503.93,1370.08 r90 bottom (schematic designator C12_FP)
C16 "0.1uF 16V" CAPC1005-STAR 1433.07,1370.08 r90 bottom (schematic designator C13_FP)
C17 "0.1uF 16V" CAPC1005-STAR 1417.32,1421.26 r0 bottom (schematic designator C14_FP)
C18 "0.1uF 16V" CAPC1005-STAR 1417.32,1492.12 r0 bottom (schematic designator C15_FP)
C19 "0.1uF 16V" CAPC1005-STAR 1417.32,1527.56 r0 bottom (schematic designator C16_FP)
C20 "10nF 16V" CAPC1005-STAR 1433.07,1582.67 r270 bottom (schematic designator C17_FP)
C21 "10nF 16V" CAPC1005-STAR 1503.93,1582.67 r270 bottom (schematic designator C18_FP)
C22 "10nF 16V" CAPC1005-STAR 1574.8,1582.67 r270 bottom (schematic designator C19_FP)
C23 "10nF 16V" CAPC1005-STAR 1645.67,1582.67 r270 bottom (schematic designator C20_FP)
C24 "10nF 16V" CAPC1005-STAR 1629.92,1531.49 r180 bottom (schematic designator C21_FP)
C25 "10nF 16V" CAPC1005-STAR 1629.92,1460.63 r180 bottom (schematic designator C22_FP)
C26 "10nF 16V" CAPC1005-STAR 1610.23,1370.08 r90 bottom (schematic designator C23_FP)
C27 "10nF 16V" CAPC1005-STAR 1539.37,1370.08 r90 bottom (schematic designator C24_FP)
C28 "10nF 16V" CAPC1005-STAR 1468.5,1370.08 r90 bottom (schematic designator C25_FP)
C29 "10nF 16V" CAPC1005-STAR 1397.64,1370.08 r90 bottom (schematic designator C26_FP)
C30 "10nF 16V" CAPC1005-STAR 1417.32,1456.69 r0 bottom (schematic designator C27_FP)
C31 "10nF 16V" CAPC1005-STAR 1523.62,1692.91 r90 bottom (schematic designator C28_FP)
C32 "10nF 16V" CAPC1005-STAR 1307.08,1476.37 r180 bottom (schematic designator C29_FP)
C33 "10nF 16V" CAPC1005-STAR 1523.62,1259.84 r270 bottom (schematic designator C30_FP)
C34 "10nF 16V" CAPC1005-STAR 1740.15,1476.37 r0 bottom (schematic designator C31_FP)
C35 "10uF 10V" CAPC2012-STAR 1236.22,2153.54 r0 bottom (schematic designator C38_FP)
C36 "10uF 10V" CAPC2012-STAR 889.76,1716.53 r270 bottom (schematic designator C39_FP)
C37 "10uF 10V" CAPC2012-STAR 1826.89,2152.54 r180 bottom (schematic designator C40_FP)
C38 "10uF 10V" CAPC2012-STAR 889.76,1188.97 r90 bottom (schematic designator C41_FP)
C39 "10uF 10V" CAPC2012-STAR 2153.54,1708.66 r270 bottom (schematic designator C42_FP)
C40 "10uF 10V" CAPC2012-STAR 2157.48,1185.04 r90 bottom (schematic designator C43_FP)
C41 "10uF 10V" CAPC2012-STAR 1795.27,791.34 r180 bottom (schematic designator C44_FP)
C42 "10uF 10V" CAPC2012-STAR 1248.03,791.34 r0 bottom (schematic designator C45_FP)
C43 "0.1uF 16V" CAPC1005-STAR 1523.63,1082.68 r270 bottom (schematic designator C46_FP)
C44 "0.1uF 16V" CAPC1005-STAR 1129.92,1476.38 r180 bottom (schematic designator C47_FP)
C45 "0.1uF 16V" CAPC1005-STAR 1208.66,1476.38 r0 bottom (schematic designator C48_FP)
C46 "0.1uF 16V" CAPC1005-STAR 1917.33,1476.38 r0 bottom (schematic designator C49_FP)
C47 "0.1uF 16V" CAPC1005-STAR 1523.63,1791.34 r270 bottom (schematic designator C50_FP)
C48 "0.1uF 16V" CAPC1005-STAR 1523.62,1161.41 r90 bottom (schematic designator C51_FP)
C49 "0.1uF 16V" CAPC1005-STAR 1523.62,1870.08 r90 bottom (schematic designator C52_FP)
C50 "0.1uF 16V" CAPC1005-STAR 1838.59,1476.38 r180 bottom (schematic designator C53_FP)
C51 "0.1uF 16V" CAPC1005-STAR 2015.75,1279.53 r0 bottom (schematic designator C54_FP)
C52 "0.1uF 16V" CAPC1005-STAR 2015.75,1122.05 r0 bottom (schematic designator C55_FP)
C53 "0.1uF 16V" CAPC1005-STAR 2015.74,1515.74 r0 bottom (schematic designator C56_FP)
C54 "0.1uF 16V" CAPC1005-STAR 2015.75,1200.79 r0 bottom (schematic designator C57_FP)
C55 "0.1uF 16V" CAPC1005-STAR 2015.75,1673.23 r0 bottom (schematic designator C58_FP)
C56 "0.1uF 16V" CAPC1005-STAR 2015.75,1751.97 r0 bottom (schematic designator C59_FP)
C57 "0.1uF 16V" CAPC1005-STAR 2015.75,1830.71 r0 bottom (schematic designator C60_FP)
C58 "0.1uF 16V" CAPC1005-STAR 2015.74,1594.49 r0 bottom (schematic designator C61_FP)
C59 "10nF 16V" CAPC1005-STAR 1641.73,1968.5 r90 bottom (schematic designator C62_FP)
C60 "10nF 16V" CAPC1005-STAR 1877.95,1968.5 r90 bottom (schematic designator C63_FP)
C61 "10nF 16V" CAPC1005-STAR 1799.21,1968.5 r90 bottom (schematic designator C64_FP)
C62 "10nF 16V" CAPC1005-STAR 1720.47,1968.5 r90 bottom (schematic designator C65_FP)
C63 "10nF 16V" CAPC1005-STAR 1169.29,1968.5 r90 bottom (schematic designator C66_FP)
C64 "10nF 16V" CAPC1005-STAR 1326.77,1968.5 r90 bottom (schematic designator C67_FP)
C65 "10nF 16V" CAPC1005-STAR 1405.51,1968.5 r90 bottom (schematic designator C68_FP)
C66 "10nF 16V" CAPC1005-STAR 1248.03,1968.5 r90 bottom (schematic designator C69_FP)
C67 "10nF 16V" CAPC1005-STAR 1031.5,1751.97 r180 bottom (schematic designator C70_FP)
C68 "10nF 16V" CAPC1005-STAR 1031.5,1594.49 r180 bottom (schematic designator C71_FP)
C69 "10nF 16V" CAPC1005-STAR 1031.5,1200.79 r180 bottom (schematic designator C72_FP)
C70 "10nF 16V" CAPC1005-STAR 1031.5,1122.05 r180 bottom (schematic designator C73_FP)
C71 "10nF 16V" CAPC1005-STAR 1031.5,1673.23 r180 bottom (schematic designator C74_FP)
C72 "10nF 16V" CAPC1005-STAR 1031.5,1279.53 r180 bottom (schematic designator C75_FP)
C73 "10nF 16V" CAPC1005-STAR 1031.5,1830.71 r180 bottom (schematic designator C76_FP)
C74 "10nF 16V" CAPC1005-STAR 1031.5,1358.27 r180 bottom (schematic designator C77_FP)
C75 "10nF 16V" CAPC1005-STAR 1169.29,984.25 r270 bottom (schematic designator C78_FP)
C76 "10nF 16V" CAPC1005-STAR 1641.73,984.25 r270 bottom (schematic designator C79_FP)
C77 "10nF 16V" CAPC1005-STAR 1799.21,984.25 r270 bottom (schematic designator C80_FP)
C78 "10nF 16V" CAPC1005-STAR 1405.51,984.25 r270 bottom (schematic designator C81_FP)
C79 "10nF 16V" CAPC1005-STAR 1720.47,984.25 r270 bottom (schematic designator C82_FP)
C80 "10nF 16V" CAPC1005-STAR 1326.77,984.25 r270 bottom (schematic designator C83_FP)
C81 "10nF 16V" CAPC1005-STAR 1248.03,984.25 r270 bottom (schematic designator C84_FP)
C82 "10nF 16V" CAPC1005-STAR 1877.95,984.25 r270 bottom (schematic designator C85_FP)
C83 "10nF 16V" CAPC1005-STAR 1956.7,1968.5 r90 bottom (schematic designator C86_FP)
C84 "10nF 16V" CAPC1005-STAR 1562.99,984.25 r270 bottom (schematic designator C87_FP)
C85 "10nF 16V" CAPC1005-STAR 1090.55,984.25 r270 bottom (schematic designator C88_FP)
C86 "10nF 16V" CAPC1005-STAR 1031.5,1043.31 r180 bottom (schematic designator C89_FP)
C87 "10nF 16V" CAPC1005-STAR 1484.25,984.25 r270 bottom (schematic designator C90_FP)
C88 "10nF 16V" CAPC1005-STAR 2015.75,1043.31 r0 bottom (schematic designator C91_FP)
C89 "10nF 16V" CAPC1005-STAR 2015.75,1909.45 r0 bottom (schematic designator C92_FP)
C90 "10nF 16V" CAPC1005-STAR 1956.7,984.25 r270 bottom (schematic designator C93_FP)
C91 "10nF 16V" CAPC1005-STAR 1484.25,1968.5 r90 bottom (schematic designator C94_FP)
C92 "10nF 16V" CAPC1005-STAR 1090.55,1968.5 r90 bottom (schematic designator C95_FP)
C93 "10nF 16V" CAPC1005-STAR 1031.5,1437.01 r180 bottom (schematic designator C96_FP)
C94 "10nF 16V" CAPC1005-STAR 1031.5,1515.75 r180 bottom (schematic designator C97_FP)
C95 "10nF 16V" CAPC1005-STAR 1031.5,1909.45 r180 bottom (schematic designator C98_FP)
C96 "10nF 16V" CAPC1005-STAR 2015.75,1437.01 r0 bottom (schematic designator C99_FP)
C97 "10nF 16V" CAPC1005-STAR 2015.75,1358.27 r0 bottom (schematic designator C100_FP)
C98 "10nF 16V" CAPC1005-STAR 1562.99,1968.5 r90 bottom (schematic designator C101_FP)
C99 "220uF 10V" CAPC7343-STAR 681.1,1255.9 r270 bottom (schematic designator C1_MB)
C100 "220uF 10V" CAPC7343-STAR 1870.07,2862.2 r180 bottom (schematic designator C2_MB)
C101 "0.1uF 16V" CAPC1005-STAR 1259.84,236.22 r0 bottom (schematic designator C1_SL)
C102 "0.1uF 16V" CAPC1005-STAR 2370.07,2799.21 r180 bottom (schematic designator C1)
C103 "0.1uF 16V" CAPC1005-STAR 2263.78,3233.27 r180 bottom (schematic designator C2)
C104 "10nF 16V" CAPC1005-STAR 2185.04,2969.49 r270 bottom (schematic designator C3)
C105 "10nF 16V" CAPC1005-STAR 2370.07,2842.51 r180 bottom (schematic designator C4)
C106 "10nF 16V" CAPC1005-STAR 2263.78,3186.02 r180 bottom (schematic designator C5)
C107 "0.1uF 16V" CAPC1005-STAR 2141.73,2969.49 r270 bottom (schematic designator C6)
C108 "0.1uF 16V" CAPC1005-STAR 1342.52,874.01 r270 bottom (schematic designator C2_PL)
C109 "10nF 16V" CAPC1005-STAR 1279.52,874.01 r270 bottom (schematic designator C3_PL)
C110 "1nF 50V" CAPC1005-STAR 1216.53,874.01 r270 bottom (schematic designator C4_PL)
C111 "2.2uF 10V" CAPC1608-STAR 1429.13,909.45 r0 bottom (schematic designator C1_PL)
C112 "0.1uF 16V" CAPC1005-STAR 1751.97,2062.99 r90 bottom (schematic designator C6_PL)
C113 "10nF 16V" CAPC1005-STAR 1814.96,2062.99 r90 bottom (schematic designator C7_PL)
C114 "1nF 50V" CAPC1005-STAR 1877.95,2062.99 r90 bottom (schematic designator C8_PL)
C115 "2.2uF 10V" CAPC1608-STAR 1669.29,2035.43 r180 bottom (schematic designator C5_PL)
C116 "0.1uF 16V" CAPC1005-STAR 1303.15,2059.05 r90 bottom (schematic designator C10_PL)
C117 "10nF 16V" CAPC1005-STAR 1240.15,2059.05 r90 bottom (schematic designator C11_PL)
C118 "1nF 50V" CAPC1005-STAR 1177.16,2059.05 r90 bottom (schematic designator C12_PL)
C119 "2.2uF 10V" CAPC1608-STAR 1381.89,2035.43 r0 bottom (schematic designator C9_PL)
C120 "0.1uF 16V" CAPC1005-STAR 1751.97,889.76 r270 bottom (schematic designator C14_PL)
C121 "10nF 16V" CAPC1005-STAR 1814.96,889.76 r270 bottom (schematic designator C15_PL)
C122 "1nF 50V" CAPC1005-STAR 1877.95,889.76 r270 bottom (schematic designator C16_PL)
C123 "2.2uF 10V" CAPC1608-STAR 1700.78,885.83 r270 bottom (schematic designator C13_PL)
C124 "10uF 10V" CAPC2012-STAR 2765.75,3087.59 r0 bottom (schematic designator C23_CM)
C125 "10uF 10V" CAPC2012-STAR 2216.53,3986.21 r270 bottom (schematic designator C24_CM)
C126 "470pF 50V" CAPC1005-STAR 2944.88,1740.15 r90 top (schematic designator C2_PS)
C127 "2.2uF 10V" CAPC1608-STAR 2456.69,1692.91 r180 top (schematic designator C4_PS)
C128 "220uF 10V" CAPC7343-STAR 2814.95,2149.6 r180 top (schematic designator C3_PS)
C129 "10uF 10V" CAPC2012-STAR 2988.18,1425.19 r270 top (schematic designator C5_PS)
C130 "22uF 10V" CAPC3225-STAR 2748.03,1503.93 r180 top (schematic designator C6_PS)
C131 "10uF 10V" CAPC2012-STAR 3118.1,1795.27 r270 top (schematic designator C8_PS)
C132 "22uF 10V" CAPC3225-STAR 2637.79,1976.37 r180 top (schematic designator C1_PS)
C133 "1uF 25V" CAPC3216-STAR 2448.81,1783.46 r0 top (schematic designator C7_PS)
C134 "0.1uF 16V" CAPC1005-STAR 2149.6,4007.87 r270 top (schematic designator C1)
C135 "0.1uF 16V" CAPC1005-STAR 1535.43,3374.01 r180 top (schematic designator C2)
C136 "0.1uF 16V" CAPC1005-STAR 1279.52,3405.5 r180 bottom (schematic designator C3)
C137 "0.1uF 16V" CAPC1005-STAR 1803.15,3999.99 r90 bottom (schematic designator C4)
C138 "10nF 16V" CAPC1005-STAR 1440.94,3980.31 r180 top (schematic designator C5)
C139 "10nF 16V" CAPC1005-STAR 1629.92,3980.31 r180 top (schematic designator C6)
C140 "10nF 16V" CAPC1005-STAR 2039.37,3374.01 r180 bottom (schematic designator C7)
C141 "10nF 16V" CAPC1005-STAR 1850.39,3374.01 r180 bottom (schematic designator C8)
C142 "0.1uF 16V" CAPC1005-STAR 2915.44,1059.04 r90 top (schematic designator C1_SM)
C143 "0.1uF 16V" CAPC1005-STAR 2309.14,1055.11 r270 top (schematic designator C2_SM)
C144 "10nF 16V" CAPC1005-STAR 2915.44,980.3 r270 top (schematic designator C3_SM)
C145 "10nF 16V" CAPC1005-STAR 2259.84,1055.12 r270 top (schematic designator C4_SM)
C146 "0.1uF 16V" CAPC1005-STAR 2391.82,980.3 r270 bottom (schematic designator C1_SM)
C147 "0.1uF 16V" CAPC1005-STAR 3007.87,1133.86 r90 bottom (schematic designator C2_SM)
C148 "10nF 16V" CAPC1005-STAR 2391.82,1062.98 r90 bottom (schematic designator C3_SM)
C149 "10nF 16V" CAPC1005-STAR 3007.87,1055.12 r270 bottom (schematic designator C4_SM)
C150 "0.1uF 16V" CAPC1005-STAR 2604.05,3326.76 r0 top (schematic designator C1)
C151 "0.1uF 16V" CAPC1005-STAR 2602.36,4027.55 r180 top (schematic designator C2)
C152 "0.1uF 16V" CAPC1005-STAR 2602.36,3330.7 r0 bottom (schematic designator C3)
C153 "0.1uF 16V" CAPC1005-STAR 2665.35,4027.55 r0 bottom (schematic designator C4)
C154 "10nF 16V" CAPC1005-STAR 2604.05,3370.07 r0 top (schematic designator C5)
C155 "10nF 16V" CAPC1005-STAR 2602.08,3984.25 r180 top (schematic designator C6)
C156 "10nF 16V" CAPC1005-STAR 2602.36,3370.07 r0 bottom (schematic designator C7)
C157 "10nF 16V" CAPC1005-STAR 2665.35,3984.25 r0 bottom (schematic designator C8)
HDR_B1 "MOLEX - 54075-1009" 54075 1893.7,472.44 r0 bottom locked (schematic designator HDR_B)
HDR_L1 "MOLEX - 54075-1009" 54075 307.09,1472.44 r270 bottom locked (schematic designator HDR_L)
HDR_T1 "MOLEX - 54075-1009" 54075 1893.7,2472.44 r0 bottom locked (schematic designator HDR_T)
L1 "1K at 100MHz 300mA" INDC2012-STAR 1437.01,838.58 r180 bottom (schematic designator L2_PL)
L2 "1K at 100MHz 300mA" INDC2012-STAR 1625.98,2106.29 r0 bottom (schematic designator L3_PL)
L3 "1K at 100MHz 300mA" INDC2012-STAR 1409.45,2106.29 r180 bottom (schematic designator L4_PL)
L4 "1K at 100MHz 300mA" INDC2012-STAR 1606.3,893.7 r0 bottom (schematic designator L5_PL)
L5 "2u2, 15A, 4R2, SMD" IND-EPCOS-SMD-B82559 2944.88,1649.6 r90 bottom (schematic designator L1_PS)
LED1 "GREEN" LED2012-STAR 1261.81,169.29 r180 top (schematic designator LED2_SL)
LED2 "RED" LED2012-STAR 1974.41,169.29 r180 top (schematic designator LED1_SL)
MH1 "MOUNTING HOLE 3MM" MOUNTING_HOLE_3MM 1618.11,129.92 r180 top locked
MH2 "MOUNTING HOLE 3MM" MOUNTING_HOLE_3MM 129.92,4326.77 r180 top locked
MH3 "MOUNTING HOLE 3MM" MOUNTING_HOLE_3MM 3106.3,4326.77 r180 top locked
NT1 "Net Tie SMT2" NETTIE-SMT2-8X8 1626.22,2700.43 r90 bottom net-tie
NT2 "Net Tie SMT2" NETTIE-SMT2-8X8 1464.21,257.64 r0 bottom net-tie (schematic designator NT6)
NT3 "Net Tie SMT2" NETTIE-SMT2-8X8 1562.76,2165 r90 top net-tie (schematic designator NT8)
NT4 "Net Tie SMT2" NETTIE-SMT2-8X8 1752.2,2680.73 r90 bottom net-tie (schematic designator NT2)
NT5 "Net Tie SMT2" NETTIE-SMT2-8X8 1720.7,2680.73 r90 bottom net-tie (schematic designator NT3)
NT6 "Net Tie SMT2" NETTIE-SMT2-8X8 1689.21,2680.73 r90 bottom net-tie (schematic designator NT4)
NT7 "Net Tie SMT2" NETTIE-SMT2-8X8 1657.71,2680.73 r90 bottom net-tie (schematic designator NT5)
NT8 "Net Tie SMT2" NETTIE-SMT2-8X8 2519.44,1987.83 r90 top net-tie (schematic designator NT7)
PBFREE "" LEAD_FREE_S 292.32,3631.89 r180 bottom
R1 "270R 1%" RESC1005-STAR 1248.03,169.29 r180 bottom (schematic designator R2_SL)
R2 "270R 1%" RESC1005-STAR 1974.41,169.29 r180 bottom (schematic designator R1_SL)
R3 "4K7 1%" RESC1005-STAR 1066.93,2153.54 r270 bottom (schematic designator R1)
R4 "4K7 1%" RESC1005-STAR 964.56,2051.18 r270 bottom (schematic designator R2)
R5 "4K7 1%" RESC1005-STAR 2251.96,1350.39 r0 bottom (schematic designator R3)
R6 "100R 1%" RESC1005-STAR 913.38,2153.54 r270 bottom (schematic designator R12)
R7 "100R 1%" RESC1005-STAR 862.2,2153.54 r270 bottom (schematic designator R14)
R8 "4K7 1%" RESC1005-STAR 2251.96,1307.08 r0 bottom (schematic designator R4)
R9 "100R 1%" RESC1005-STAR 1015.75,2051.18 r270 bottom (schematic designator R22)
R10 "100R 1%" RESC1005-STAR 811.02,2153.54 r270 bottom (schematic designator R20)
R11 "4K7 1%" RESC1005-STAR 913.38,2051.18 r270 bottom (schematic designator R7)
R12 "100R 1%" RESC1005-STAR 2161.41,1393.7 r180 bottom (schematic designator R18)
R13 "100R 1%" RESC1005-STAR 2161.41,1437 r180 bottom (schematic designator R23)
R14 "100R 1%" RESC1005-STAR 1015.75,2153.54 r270 bottom (schematic designator R24)
R15 "100R 1%" RESC1005-STAR 2161.41,1307.08 r180 bottom (schematic designator R25)
R16 "100R 1%" RESC1005-STAR 862.2,2051.18 r270 bottom (schematic designator R26)
R17 "100R 1%" RESC1005-STAR 964.56,2153.54 r270 bottom (schematic designator R27)
R18 "100R 1%" RESC1005-STAR 2161.41,1350.39 r180 bottom (schematic designator R8)
R19 "10R 1%" RESC1005-STAR 2492.12,1622.04 r90 top (schematic designator R2_PS)
R20 "2K7 1%" RESC1005-STAR 2787.4,1866.14 r0 top (schematic designator R1_PS)
R21 "27K 1%" RESC1005-STAR 2889.76,1866.14 r0 top (schematic designator R3_PS)
R22 "2K7 1%" RESC1005-STAR 2992.12,1866.14 r0 top (schematic designator R4_PS)
R23 "100K 1%" RESC1005-STAR 2992.12,1814.96 r0 top (schematic designator R5_PS)
RN1 "RESNET 4 x 100R" RESNET-1005X4 1662.99,3301.18 r90 bottom (schematic designator RN33)
RN2 "RESNET 4 x 100R" RESNET-1005X4 1366.74,3301.18 r90 bottom (schematic designator RN35)
RN3 "RESNET 4 x 100R" RESNET-1005X4 1559.66,4025.59 r90 bottom (schematic designator RN37)
RN4 "RESNET 4 x 100R" RESNET-1005X4 1804.73,3301.18 r270 bottom (schematic designator RN34)
RN5 "RESNET 4 x 100R" RESNET-1005X4 1701.39,4025.59 r270 bottom (schematic designator RN38)
RN6 "RESNET 4 x 100R" RESNET-1005X4 1508.47,3301.18 r270 bottom (schematic designator RN36)
TP1 "GND" TestPin 2875.71,3138.67 r0 top (schematic designator TP0)
TP2 "3V3" TestPin 2875.71,3038.67 r0 top (schematic designator TP1)
TP3 "GND" TestPin 2875.71,2938.67 r0 top (schematic designator TP2)
TP4 "5V0" TestPin 2875.71,2838.67 r0 top (schematic designator TP3)
TP5 "1V2" TestPin 2875.71,2738.67 r0 top (schematic designator TP4)
U1 "DS2406" TSOC6 2712.59,2846.45 r90 bottom
U2 "SN74LVC1G04DBV" SOT95P280-5 1397.64,165.35 r0 bottom (schematic designator U1_SL)
U3 "S29GL256N11FFIV10" BGA100P8X8-64 2370.08,3036.42 r180 top locked (schematic designator U1)
U4 "EP2C35F672C8" BGA100P26X26-672 1523.62,1476.38 r0 top locked (schematic designator U1)
U5 "MAX1831EEE" SOP63P602-16 2708.58,1720.75 r180 top locked (schematic designator U1_PS)
U6 "SDRAM-16Mx16" TSOP80P1176-54 1740.16,3677.16 r0 top (schematic designator U1)
U7 "SDRAM-16Mx16" TSOP80P1176-54 1740.16,3677.17 r180 bottom locked (schematic designator U2)
U8 "SRAM-256Kx16" TSOP80P1176-44 2612.3,1059.05 r90 top (schematic designator U1_SM)
U9 "SRAM-256Kx16" TSOP80P1176-44 2702.84,1059.04 r90 bottom (schematic designator U1_SM)
U10 "SRAM-256Kx16" TSOP80P1176-44 2602.36,3677.16 r0 top (schematic designator U1)
U11 "SRAM-256Kx16" TSOP80P1176-44 2665.35,3677.17 r180 bottom locked (schematic designator U2)

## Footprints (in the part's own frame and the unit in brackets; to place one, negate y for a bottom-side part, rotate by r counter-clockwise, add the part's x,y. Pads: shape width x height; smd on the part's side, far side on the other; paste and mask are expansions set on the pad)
54075 [mm]
  rect 0.5x1.9 smd: 1(-19.6,3.4) 2(-19.6,-3.4) 3(-18.8,3.4) 4(-18.8,-3.4) 5(-18,3.4) 6(-18,-3.4) 7(-17.2,3.4) 8(-17.2,-3.4) 9(-16.4,3.4) 10(-16.4,-3.4) 11(-15.6,3.4) 12(-15.6,-3.4) 13(-14.8,3.4) 14(-14.8,-3.4) 15(-14,3.4) 16(-14,-3.4) 17(-13.2,3.4) 18(-13.2,-3.4) 19(-12.4,3.4) 20(-12.4,-3.4) 21(-11.6,3.4) 22(-11.6,-3.4) 23(-10.8,3.4) 24(-10.8,-3.4) 25(-10,3.4) 26(-10,-3.4) 27(-9.2,3.4) 28(-9.2,-3.4) 29(-8.4,3.4) 30(-8.4,-3.4) 31(-7.6,3.4) 32(-7.6,-3.4) 33(-6.8,3.4) 34(-6.8,-3.4) 35(-6,3.4) 36(-6,-3.4) 37(-5.2,3.4) 38(-5.2,-3.4) 39(-4.4,3.4) 40(-4.4,-3.4) 41(-3.6,3.4) 42(-3.6,-3.4) 43(-2.8,3.4) 44(-2.8,-3.4) 45(-2,3.4) 46(-2,-3.4) 47(-1.2,3.4) 48(-1.2,-3.4) 49(-0.4,3.4) 50(-0.4,-3.4) 51(0.4,3.4) 52(0.4,-3.4) 53(1.2,3.4) 54(1.2,-3.4) 55(2,3.4) 56(2,-3.4) 57(2.8,3.4) 58(2.8,-3.4) 59(3.6,3.4) 60(3.6,-3.4) 61(4.4,3.4) 62(4.4,-3.4) 63(5.2,3.4) 64(5.2,-3.4) 65(6,3.4) 66(6,-3.4) 67(6.8,3.4) 68(6.8,-3.4) 69(7.6,3.4) 70(7.6,-3.4) 71(8.4,3.4) 72(8.4,-3.4) 73(9.2,3.4) 74(9.2,-3.4) 75(10,3.4) 76(10,-3.4) 77(10.8,3.4) 78(10.8,-3.4) 79(11.6,3.4) 80(11.6,-3.4) 81(12.4,3.4) 82(12.4,-3.4) 83(13.2,3.4) 84(13.2,-3.4) 85(14,3.4) 86(14,-3.4) 87(14.8,3.4) 88(14.8,-3.4) 89(15.6,3.4) 90(15.6,-3.4) 91(16.4,3.4) 92(16.4,-3.4) 93(17.2,3.4) 94(17.2,-3.4) 95(18,3.4) 96(18,-3.4) 97(18.8,3.4) 98(18.8,-3.4) 99(19.6,3.4) 100(19.6,-3.4)
  round 1.6 hole 0.7: MH1(-26.7,4.2) MH2(-25.9,-4.2) MH3(26.7,4.2) MH4(25.9,-4.2)
  round 4.8 hole 5.1 unplated: MH5(-26.3,0) MH6(26.3,0)
  Top Layer keep-out region: -20.15,2.15 20.15,2.15 20.15,-2.15 -20.15,-2.15
  silkscreen extent -30.35,-4.4 30.35,5.02
BGA100P8X8-64 [mm] "AMD 64-Ball Fortfied Ball grid Array (FBGA)"
  round 0.5 smd: A1(-3.5,-3.5) A2(-3.5,-2.5) A3(-3.5,-1.5) A4(-3.5,-0.5) A5(-3.5,0.5) A6(-3.5,1.5) A7(-3.5,2.5) A8(-3.5,3.5) B1(-2.5,-3.5) B2(-2.5,-2.5) B3(-2.5,-1.5) B4(-2.5,-0.5) B5(-2.5,0.5) B6(-2.5,1.5) B7(-2.5,2.5) B8(-2.5,3.5) C1(-1.5,-3.5) C2(-1.5,-2.5) C3(-1.5,-1.5) C4(-1.5,-0.5) C5(-1.5,0.5) C6(-1.5,1.5) C7(-1.5,2.5) C8(-1.5,3.5) D1(-0.5,-3.5) D2(-0.5,-2.5) D3(-0.5,-1.5) D4(-0.5,-0.5) D5(-0.5,0.5) D6(-0.5,1.5) D7(-0.5,2.5) D8(-0.5,3.5) E1(0.5,-3.5) E2(0.5,-2.5) E3(0.5,-1.5) E4(0.5,-0.5) E5(0.5,0.5) E6(0.5,1.5) E7(0.5,2.5) E8(0.5,3.5) F1(1.5,-3.5) F2(1.5,-2.5) F3(1.5,-1.5) F4(1.5,-0.5) F5(1.5,0.5) F6(1.5,1.5) F7(1.5,2.5) F8(1.5,3.5) G1(2.5,-3.5) G2(2.5,-2.5) G3(2.5,-1.5) G4(2.5,-0.5) G5(2.5,0.5) G6(2.5,1.5) G7(2.5,2.5) G8(2.5,3.5) H1(3.5,-3.5) H2(3.5,-2.5) H3(3.5,-1.5) H4(3.5,-0.5) H5(3.5,0.5) H6(3.5,1.5) H7(3.5,2.5) H8(3.5,3.5)
  silkscreen extent -6.5,-6.32 6.5,5.5
BGA100P26X26-672 [mm] "672-Ball FineLine Ball Grid Array (FBGA672)"
  round 0.5 smd: A2(-11.5,12.5) A3(-10.5,12.5) A4(-9.5,12.5) A5(-8.5,12.5) A6(-7.5,12.5) A7(-6.5,12.5) A8(-5.5,12.5) A9(-4.5,12.5) A10(-3.5,12.5) A11(-2.5,12.5) A12(-1.5,12.5) A13(-0.5,12.5) A14(0.5,12.5) A15(1.5,12.5) A16(2.5,12.5) A17(3.5,12.5) A18(4.5,12.5) A19(5.5,12.5) A20(6.5,12.5) A21(7.5,12.5) A22(8.5,12.5) A23(9.5,12.5) A24(10.5,12.5) A25(11.5,12.5) AA1(-12.5,-7.5) AA2(-11.5,-7.5) AA3(-10.5,-7.5) AA4(-9.5,-7.5) AA5(-8.5,-7.5) AA6(-7.5,-7.5) AA7(-6.5,-7.5) AA8(-5.5,-7.5) AA9(-4.5,-7.5) AA10(-3.5,-7.5) AA11(-2.5,-7.5) AA12(-1.5,-7.5) AA13(-0.5,-7.5) AA14(0.5,-7.5) AA15(1.5,-7.5) AA16(2.5,-7.5) AA17(3.5,-7.5) AA18(4.5,-7.5) AA19(5.5,-7.5) AA20(6.5,-7.5) AA21(7.5,-7.5) AA22(8.5,-7.5) AA23(9.5,-7.5) AA24(10.5,-7.5) AA25(11.5,-7.5) AA26(12.5,-7.5) AB1(-12.5,-8.5) AB2(-11.5,-8.5) AB3(-10.5,-8.5) AB4(-9.5,-8.5) AB5(-8.5,-8.5) AB6(-7.5,-8.5) AB7(-6.5,-8.5) AB8(-5.5,-8.5) AB9(-4.5,-8.5) AB10(-3.5,-8.5) AB11(-2.5,-8.5) AB12(-1.5,-8.5) AB13(-0.5,-8.5) AB14(0.5,-8.5) AB15(1.5,-8.5) AB16(2.5,-8.5) AB17(3.5,-8.5) AB18(4.5,-8.5) AB19(5.5,-8.5) AB20(6.5,-8.5) AB21(7.5,-8.5) AB22(8.5,-8.5) AB23(9.5,-8.5) AB24(10.5,-8.5) AB25(11.5,-8.5) AB26(12.5,-8.5) AC1(-12.5,-9.5) AC2(-11.5,-9.5) AC3(-10.5,-9.5) AC4(-9.5,-9.5) AC5(-8.5,-9.5) AC6(-7.5,-9.5) AC7(-6.5,-9.5) AC8(-5.5,-9.5) AC9(-4.5,-9.5) AC10(-3.5,-9.5) AC11(-2.5,-9.5) AC12(-1.5,-9.5) AC13(-0.5,-9.5) AC14(0.5,-9.5) AC15(1.5,-9.5) AC16(2.5,-9.5) AC17(3.5,-9.5) AC18(4.5,-9.5) AC19(5.5,-9.5) AC20(6.5,-9.5) AC21(7.5,-9.5) AC22(8.5,-9.5) AC23(9.5,-9.5) AC24(10.5,-9.5) AC25(11.5,-9.5) AC26(12.5,-9.5) AD1(-12.5,-10.5) AD2(-11.5,-10.5) AD3(-10.5,-10.5) AD4(-9.5,-10.5) AD5(-8.5,-10.5) AD6(-7.5,-10.5) AD7(-6.5,-10.5) AD8(-5.5,-10.5) AD9(-4.5,-10.5) AD10(-3.5,-10.5) AD11(-2.5,-10.5) AD12(-1.5,-10.5) AD13(-0.5,-10.5) AD14(0.5,-10.5) AD15(1.5,-10.5) AD16(2.5,-10.5) AD17(3.5,-10.5) AD18(4.5,-10.5) AD19(5.5,-10.5) AD20(6.5,-10.5) AD21(7.5,-10.5) AD22(8.5,-10.5) AD23(9.5,-10.5) AD24(10.5,-10.5) AD25(11.5,-10.5) AD26(12.5,-10.5) AE1(-12.5,-11.5) AE2(-11.5,-11.5) AE3(-10.5,-11.5) AE4(-9.5,-11.5) AE5(-8.5,-11.5) AE6(-7.5,-11.5) AE7(-6.5,-11.5) AE8(-5.5,-11.5) AE9(-4.5,-11.5) AE10(-3.5,-11.5) AE11(-2.5,-11.5) AE12(-1.5,-11.5) AE13(-0.5,-11.5) AE14(0.5,-11.5) AE15(1.5,-11.5) AE16(2.5,-11.5) AE17(3.5,-11.5) AE18(4.5,-11.5) AE19(5.5,-11.5) AE20(6.5,-11.5) AE21(7.5,-11.5) AE22(8.5,-11.5) AE23(9.5,-11.5) AE24(10.5,-11.5) AE25(11.5,-11.5) AE26(12.5,-11.5) AF2(-11.5,-12.5) AF3(-10.5,-12.5) AF4(-9.5,-12.5) AF5(-8.5,-12.5) AF6(-7.5,-12.5) AF7(-6.5,-12.5) AF8(-5.5,-12.5) AF9(-4.5,-12.5) AF10(-3.5,-12.5) AF11(-2.5,-12.5) AF12(-1.5,-12.5) AF13(-0.5,-12.5) AF14(0.5,-12.5) AF15(1.5,-12.5) AF16(2.5,-12.5) AF17(3.5,-12.5) AF18(4.5,-12.5) AF19(5.5,-12.5) AF20(6.5,-12.5) AF21(7.5,-12.5) AF22(8.5,-12.5) AF23(9.5,-12.5) AF24(10.5,-12.5) AF25(11.5,-12.5) B1(-12.5,11.5) B2(-11.5,11.5) B3(-10.5,11.5) B4(-9.5,11.5) B5(-8.5,11.5) B6(-7.5,11.5) B7(-6.5,11.5) B8(-5.5,11.5) B9(-4.5,11.5) B10(-3.5,11.5) B11(-2.5,11.5) B12(-1.5,11.5) B13(-0.5,11.5) B14(0.5,11.5) B15(1.5,11.5) B16(2.5,11.5) B17(3.5,11.5) B18(4.5,11.5) B19(5.5,11.5) B20(6.5,11.5) B21(7.5,11.5) B22(8.5,11.5) B23(9.5,11.5) B24(10.5,11.5) B25(11.5,11.5) B26(12.5,11.5) C1(-12.5,10.5) C2(-11.5,10.5) C3(-10.5,10.5) C4(-9.5,10.5) C5(-8.5,10.5) C6(-7.5,10.5) C7(-6.5,10.5) C8(-5.5,10.5) C9(-4.5,10.5) C10(-3.5,10.5) C11(-2.5,10.5) C12(-1.5,10.5) C13(-0.5,10.5) C14(0.5,10.5) C15(1.5,10.5) C16(2.5,10.5) C17(3.5,10.5) C18(4.5,10.5) C19(5.5,10.5) C20(6.5,10.5) C21(7.5,10.5) C22(8.5,10.5) C23(9.5,10.5) C24(10.5,10.5) C25(11.5,10.5) C26(12.5,10.5) D1(-12.5,9.5) D2(-11.5,9.5) D3(-10.5,9.5) D4(-9.5,9.5) D5(-8.5,9.5) D6(-7.5,9.5) D7(-6.5,9.5) D8(-5.5,9.5) D9(-4.5,9.5) D10(-3.5,9.5) D11(-2.5,9.5) D12(-1.5,9.5) D13(-0.5,9.5) D14(0.5,9.5) D15(1.5,9.5) D16(2.5,9.5) D17(3.5,9.5) D18(4.5,9.5) D19(5.5,9.5) D20(6.5,9.5) D21(7.5,9.5) D22(8.5,9.5) D23(9.5,9.5) D24(10.5,9.5) D25(11.5,9.5) D26(12.5,9.5) E1(-12.5,8.5) E2(-11.5,8.5) E3(-10.5,8.5) E4(-9.5,8.5) E5(-8.5,8.5) E6(-7.5,8.5) E7(-6.5,8.5) E8(-5.5,8.5) E9(-4.5,8.5) E10(-3.5,8.5) E11(-2.5,8.5) E12(-1.5,8.5) E13(-0.5,8.5) E14(0.5,8.5) E15(1.5,8.5) E16(2.5,8.5) E17(3.5,8.5) E18(4.5,8.5) E19(5.5,8.5) E20(6.5,8.5) E21(7.5,8.5) E22(8.5,8.5) E23(9.5,8.5) E24(10.5,8.5) E25(11.5,8.5) E26(12.5,8.5) F1(-12.5,7.5) F2(-11.5,7.5) F3(-10.5,7.5) F4(-9.5,7.5) F5(-8.5,7.5) F6(-7.5,7.5) F7(-6.5,7.5) F8(-5.5,7.5) F9(-4.5,7.5) F10(-3.5,7.5) F11(-2.5,7.5) F12(-1.5,7.5) F13(-0.5,7.5) F14(0.5,7.5) F15(1.5,7.5) F16(2.5,7.5) F17(3.5,7.5) F18(4.5,7.5) F19(5.5,7.5) F20(6.5,7.5) F21(7.5,7.5) F22(8.5,7.5) F23(9.5,7.5) F24(10.5,7.5) F25(11.5,7.5) F26(12.5,7.5) G1(-12.5,6.5) G2(-11.5,6.5) G3(-10.5,6.5) G4(-9.5,6.5) G5(-8.5,6.5) G6(-7.5,6.5) G7(-6.5,6.5) G8(-5.5,6.5) G9(-4.5,6.5) G10(-3.5,6.5) G11(-2.5,6.5) G12(-1.5,6.5) G13(-0.5,6.5) G14(0.5,6.5) G15(1.5,6.5) G16(2.5,6.5) G17(3.5,6.5) G18(4.5,6.5) G19(5.5,6.5) G20(6.5,6.5) G21(7.5,6.5) G22(8.5,6.5) G23(9.5,6.5) G24(10.5,6.5) G25(11.5,6.5) G26(12.5,6.5) H1(-12.5,5.5) H2(-11.5,5.5) H3(-10.5,5.5) H4(-9.5,5.5) H5(-8.5,5.5) H6(-7.5,5.5) H7(-6.5,5.5) H8(-5.5,5.5) H9(-4.5,5.5) H10(-3.5,5.5) H11(-2.5,5.5) H12(-1.5,5.5) H13(-0.5,5.5) H14(0.5,5.5) H15(1.5,5.5) H16(2.5,5.5) H17(3.5,5.5) H18(4.5,5.5) H19(5.5,5.5) H20(6.5,5.5) H21(7.5,5.5) H22(8.5,5.5) H23(9.5,5.5) H24(10.5,5.5) H25(11.5,5.5) H26(12.5,5.5) J1(-12.5,4.5) J2(-11.5,4.5) J3(-10.5,4.5) J4(-9.5,4.5) J5(-8.5,4.5) J6(-7.5,4.5) J7(-6.5,4.5) J8(-5.5,4.5) J9(-4.5,4.5) J10(-3.5,4.5) J11(-2.5,4.5) J12(-1.5,4.5) J13(-0.5,4.5) J14(0.5,4.5) J15(1.5,4.5) J16(2.5,4.5) J17(3.5,4.5) J18(4.5,4.5) J19(5.5,4.5) J20(6.5,4.5) J21(7.5,4.5) J22(8.5,4.5) J23(9.5,4.5) J24(10.5,4.5) J25(11.5,4.5) J26(12.5,4.5) K1(-12.5,3.5) K2(-11.5,3.5) K3(-10.5,3.5) K4(-9.5,3.5) K5(-8.5,3.5) K6(-7.5,3.5) K7(-6.5,3.5) K8(-5.5,3.5) K9(-4.5,3.5) K10(-3.5,3.5) K11(-2.5,3.5) K12(-1.5,3.5) K13(-0.5,3.5) K14(0.5,3.5) K15(1.5,3.5) K16(2.5,3.5) K17(3.5,3.5) K18(4.5,3.5) K19(5.5,3.5) K20(6.5,3.5) K21(7.5,3.5) K22(8.5,3.5) K23(9.5,3.5) K24(10.5,3.5) K25(11.5,3.5) K26(12.5,3.5) L1(-12.5,2.5) L2(-11.5,2.5) L3(-10.5,2.5) L4(-9.5,2.5) L5(-8.5,2.5) L6(-7.5,2.5) L7(-6.5,2.5) L8(-5.5,2.5) L9(-4.5,2.5) L10(-3.5,2.5) L11(-2.5,2.5) L12(-1.5,2.5) L13(-0.5,2.5) L14(0.5,2.5) L15(1.5,2.5) L16(2.5,2.5) L17(3.5,2.5) L18(4.5,2.5) L19(5.5,2.5) L20(6.5,2.5) L21(7.5,2.5) L22(8.5,2.5) L23(9.5,2.5) L24(10.5,2.5) L25(11.5,2.5) L26(12.5,2.5) M1(-12.5,1.5) M2(-11.5,1.5) M3(-10.5,1.5) M4(-9.5,1.5) M5(-8.5,1.5) M6(-7.5,1.5) M7(-6.5,1.5) M8(-5.5,1.5) M9(-4.5,1.5) M10(-3.5,1.5) M11(-2.5,1.5) M12(-1.5,1.5) M13(-0.5,1.5) M14(0.5,1.5) M15(1.5,1.5) M16(2.5,1.5) M17(3.5,1.5) M18(4.5,1.5) M19(5.5,1.5) M20(6.5,1.5) M21(7.5,1.5) M22(8.5,1.5) M23(9.5,1.5) M24(10.5,1.5) M25(11.5,1.5) M26(12.5,1.5) N1(-12.5,0.5) N2(-11.5,0.5) N3(-10.5,0.5) N4(-9.5,0.5) N5(-8.5,0.5) N6(-7.5,0.5) N7(-6.5,0.5) N8(-5.5,0.5) N9(-4.5,0.5) N10(-3.5,0.5) N11(-2.5,0.5) N12(-1.5,0.5) N13(-0.5,0.5) N14(0.5,0.5) N15(1.5,0.5) N16(2.5,0.5) N17(3.5,0.5) N18(4.5,0.5) N19(5.5,0.5) N20(6.5,0.5) N21(7.5,0.5) N22(8.5,0.5) N23(9.5,0.5) N24(10.5,0.5) N25(11.5,0.5) N26(12.5,0.5) P1(-12.5,-0.5) P2(-11.5,-0.5) P3(-10.5,-0.5) P4(-9.5,-0.5) P5(-8.5,-0.5) P6(-7.5,-0.5) P7(-6.5,-0.5) P8(-5.5,-0.5) P9(-4.5,-0.5) P10(-3.5,-0.5) P11(-2.5,-0.5) P12(-1.5,-0.5) P13(-0.5,-0.5) P14(0.5,-0.5) P15(1.5,-0.5) P16(2.5,-0.5) P17(3.5,-0.5) P18(4.5,-0.5) P19(5.5,-0.5) P20(6.5,-0.5) P21(7.5,-0.5) P22(8.5,-0.5) P23(9.5,-0.5) P24(10.5,-0.5) P25(11.5,-0.5) P26(12.5,-0.5) R1(-12.5,-1.5) R2(-11.5,-1.5) R3(-10.5,-1.5) R4(-9.5,-1.5) R5(-8.5,-1.5) R6(-7.5,-1.5) R7(-6.5,-1.5) R8(-5.5,-1.5) R9(-4.5,-1.5) R10(-3.5,-1.5) R11(-2.5,-1.5) R12(-1.5,-1.5) R13(-0.5,-1.5) R14(0.5,-1.5) R15(1.5,-1.5) R16(2.5,-1.5) R17(3.5,-1.5) R18(4.5,-1.5) R19(5.5,-1.5) R20(6.5,-1.5) R21(7.5,-1.5) R22(8.5,-1.5) R23(9.5,-1.5) R24(10.5,-1.5) R25(11.5,-1.5) R26(12.5,-1.5) T1(-12.5,-2.5) T2(-11.5,-2.5) T3(-10.5,-2.5) T4(-9.5,-2.5) T5(-8.5,-2.5) T6(-7.5,-2.5) T7(-6.5,-2.5) T8(-5.5,-2.5) T9(-4.5,-2.5) T10(-3.5,-2.5) T11(-2.5,-2.5) T12(-1.5,-2.5) T13(-0.5,-2.5) T14(0.5,-2.5) T15(1.5,-2.5) T16(2.5,-2.5) T17(3.5,-2.5) T18(4.5,-2.5) T19(5.5,-2.5) T20(6.5,-2.5) T21(7.5,-2.5) T22(8.5,-2.5) T23(9.5,-2.5) T24(10.5,-2.5) T25(11.5,-2.5) T26(12.5,-2.5) U1(-12.5,-3.5) U2(-11.5,-3.5) U3(-10.5,-3.5) U4(-9.5,-3.5) U5(-8.5,-3.5) U6(-7.5,-3.5) U7(-6.5,-3.5) U8(-5.5,-3.5) U9(-4.5,-3.5) U10(-3.5,-3.5) U11(-2.5,-3.5) U12(-1.5,-3.5) U13(-0.5,-3.5) U14(0.5,-3.5) U15(1.5,-3.5) U16(2.5,-3.5) U17(3.5,-3.5) U18(4.5,-3.5) U19(5.5,-3.5) U20(6.5,-3.5) U21(7.5,-3.5) U22(8.5,-3.5) U23(9.5,-3.5) U24(10.5,-3.5) U25(11.5,-3.5) U26(12.5,-3.5) V1(-12.5,-4.5) V2(-11.5,-4.5) V3(-10.5,-4.5) V4(-9.5,-4.5) V5(-8.5,-4.5) V6(-7.5,-4.5) V7(-6.5,-4.5) V8(-5.5,-4.5) V9(-4.5,-4.5) V10(-3.5,-4.5) V11(-2.5,-4.5) V12(-1.5,-4.5) V13(-0.5,-4.5) V14(0.5,-4.5) V15(1.5,-4.5) V16(2.5,-4.5) V17(3.5,-4.5) V18(4.5,-4.5) V19(5.5,-4.5) V20(6.5,-4.5) V21(7.5,-4.5) V22(8.5,-4.5) V23(9.5,-4.5) V24(10.5,-4.5) V25(11.5,-4.5) V26(12.5,-4.5) W1(-12.5,-5.5) W2(-11.5,-5.5) W3(-10.5,-5.5) W4(-9.5,-5.5) W5(-8.5,-5.5) W6(-7.5,-5.5) W7(-6.5,-5.5) W8(-5.5,-5.5) W9(-4.5,-5.5) W10(-3.5,-5.5) W11(-2.5,-5.5) W12(-1.5,-5.5) W13(-0.5,-5.5) W14(0.5,-5.5) W15(1.5,-5.5) W16(2.5,-5.5) W17(3.5,-5.5) W18(4.5,-5.5) W19(5.5,-5.5) W20(6.5,-5.5) W21(7.5,-5.5) W22(8.5,-5.5) W23(9.5,-5.5) W24(10.5,-5.5) W25(11.5,-5.5) W26(12.5,-5.5) Y1(-12.5,-6.5) Y2(-11.5,-6.5) Y3(-10.5,-6.5) Y4(-9.5,-6.5) Y5(-8.5,-6.5) Y6(-7.5,-6.5) Y7(-6.5,-6.5) Y8(-5.5,-6.5) Y9(-4.5,-6.5) Y10(-3.5,-6.5) Y11(-2.5,-6.5) Y12(-1.5,-6.5) Y13(-0.5,-6.5) Y14(0.5,-6.5) Y15(1.5,-6.5) Y16(2.5,-6.5) Y17(3.5,-6.5) Y18(4.5,-6.5) Y19(5.5,-6.5) Y20(6.5,-6.5) Y21(7.5,-6.5) Y22(8.5,-6.5) Y23(9.5,-6.5) Y24(10.5,-6.5) Y25(11.5,-6.5) Y26(12.5,-6.5)
  round 1 on Mech7 paste-0.55 mask+1: FID1(-15,15) FID1(15,-15)
  round 1 smd paste-0.55 mask+0.762: FID1(-15,15) FID1(15,-15)
  Top Layer keep-out circle w0.2: c15,-15 r1
  Top Layer keep-out circle w0.2: c-15,15 r1
  silkscreen extent -14.27,-13.5 13.5,13.5
CAPC1005-STAR [mm] "Chip Capacitor 1005"
  rect 0.6x0.6 smd: 1(-0.525,0) 2(0.525,0)
  silkscreen extent -0.05,-0.38 0.05,0.38
CAPC1608-STAR [mm] "Capacitor SMD 0603 (1608)"
  rect 0.9x0.8 smd: 1(-0.8,0) 2(0.8,0)
  silkscreen extent 0,-0.4 0,0.4
CAPC2012-STAR [mm] "0805 Capacitor SMD - Startronics"
  rect 1x1.25 smd: 1(-1,0) 2(1,0)
  silkscreen extent -0.4,-1 0.4,1
CAPC3216-STAR [mm] "Capacitor 1206 (3216) for Startronics"
  rect 1x1.6 smd: 1(-1.45,0) 2(1.45,0)
  silkscreen extent -0.62,-1.1 0.62,1.1
CAPC3225-STAR [mm] "1210 Capacitor SMD - Startronics"
  rect 1x2.75 smd: 1(-1.5,0) 2(1.5,0)
  silkscreen extent -0.7,-1.5 0.7,1.5
CAPC7343-STAR [mm] "Capcacitor SMD 7.3 x 4.3mm (D-Case)"
  rect 2.6x2.4 smd: 1(-3.202,0.007) 2(3.198,0.007)
  silkscreen extent -5.32,-2.39 5.08,2.41
IND-EPCOS-SMD-B82559 [mm]
  rect 4.4x10.4 smd: 1(0,0) 2(8.4,0)
  silkscreen extent -2.5,-5.5 11,5.5
INDC2012-STAR [mm] "0805 Inductor SMD - Startronics"
  rect 1x1.25 smd: 1(-1,0) 2(1,0)
  silkscreen extent -0.4,-1 0.4,1
LEAD_FREE_S [mil]
  silkscreen extent -125,-125 125,125
LED2012-STAR [mm] "0805 LED SMD - Startronics"
  rect 1x1.25 smd: 1(1,0) 2(-1,0)
  silkscreen extent -2.27,-1 1.8,1
Logo-Altium [mil]
  silkscreen extent -1025,-99 -556,102
MOUNTING_HOLE_3MM [mm] "Non-plated mounting hole for 3mm screw"
  round 3.8 hole 3.4 mask+0.2: MOUNT(0,0)
  Top Layer circle w1: c0,0 r2.3
  Top Layer region: -2.8,-2.8 2.8,-2.8 2.8,2.8 -2.8,2.8
  Top Layer keep-out region: -3.3,-3.3 3.3,-3.3 3.3,3.3 -3.3,3.3
  Bottom Layer region: -2.8,-2.8 2.8,-2.8 2.8,2.8 -2.8,2.8
  Bottom Layer keep-out region: -3.3,-3.3 3.3,-3.3 3.3,3.3 -3.3,3.3
  Keep-Out Layer circle w1.2: c0,0 r2.5
NETTIE-SMT2-8X8 [mm]
  rect 0.4x0.2 smd paste-0.11 mask-0.11: 1(-0.891,-0.006) 2(-0.691,-0.006)
RESC1005-STAR [mm] "Chip Inductor 1005"
  rect 0.575x0.6 smd: 1(-0.538,0) 2(0.538,0)
  silkscreen extent -0.05,-0.38 0.05,0.38
RESNET-1005X4 [mm] "Resistor network 4 x 1005 (0402)"
  rect 0.3x0.83 smd: 1(-0.75,-0.64) 2(-0.25,-0.64) 3(0.25,-0.64) 4(0.75,-0.64) 5(0.75,0.64) 6(0.25,0.64) 7(-0.25,0.64) 8(-0.75,0.64)
  silkscreen extent -1.15,-1 1.15,1
SOP63P602-16 [mil]
  rect 82x16 smd: 1(-116,87.5) 2(-116,62) 3(-116,37.5) 4(-116,12.5) 5(-116,-12.5) 6(-116,-37.5) 7(-116,-62.5) 8(-116,-87.5) 9(116,-87.5) 10(116,-62.5) 11(116,-37.5) 12(116,-12.5) 13(116,12.5) 14(116,37.5) 15(116,62.5) 16(116,87.5)
  silkscreen extent -100,-100 60,125
SOT95P280-5 [mm] "SOT-23/SC-74A; 5 Leads; Body 3.1 x 3 mm, inc. leads (LxW max)"
  rect 0.6x1.3 smd: 1(-0.95,-1.4) 2(0,-1.4) 3(0.95,-1.4) 4(0.95,1.4)
  rect 0.6x1.25 smd: 5(-0.95,1.4)
  silkscreen extent -1.55,-0.9 1.55,0.9
TestPin [mil]
  round 60 hole 35.43: 1(0,0)
  silkscreen extent -41,-39 156,39
TSOC6 [mil]
  rect 25x71 smd: 1(-50,-75) 2(0,-75) 3(50,-75) 4(50,75) 5(0,75) 6(-50,75)
  silkscreen extent -115,-80 85,80
TSOP80P1176-44 [mm]
  rect 0.5x1.4 smd: 1(-8.4,-5.7) 2(-7.6,-5.7) 3(-6.8,-5.7) 4(-6,-5.7) 5(-5.2,-5.7) 6(-4.4,-5.7) 7(-3.6,-5.7) 8(-2.8,-5.7) 9(-2,-5.7) 10(-1.2,-5.7) 11(-0.4,-5.7) 12(0.4,-5.7) 13(1.2,-5.7) 14(2,-5.7) 15(2.8,-5.7) 16(3.6,-5.7) 17(4.4,-5.7) 18(5.2,-5.7) 19(6,-5.7) 20(6.8,-5.7) 21(7.6,-5.7) 22(8.4,-5.7) 23(8.4,5.7) 24(7.6,5.7) 25(6.8,5.7) 26(6,5.7) 27(5.2,5.7) 28(4.4,5.7) 29(3.6,5.7) 30(2.8,5.7) 31(2,5.7) 32(1.2,5.7) 33(0.4,5.7) 34(-0.4,5.7) 35(-1.2,5.7) 36(-2,5.7) 37(-2.8,5.7) 38(-3.6,5.7) 39(-4.4,5.7) 40(-5.2,5.7) 41(-6,5.7) 42(-6.8,5.7) 43(-7.6,5.7) 44(-8.4,5.7)
  silkscreen extent -9.29,-5.7 9.26,4.45
TSOP80P1176-54 [mm] "Plastic Small Outline; 54 Leads; Body Width 10.16 mm"
  rect 0.5x1.4 smd: 1(-10.4,-5.7) 2(-9.6,-5.7) 3(-8.8,-5.7) 4(-8,-5.7) 5(-7.2,-5.7) 6(-6.4,-5.7) 7(-5.6,-5.7) 8(-4.8,-5.7) 9(-4,-5.7) 10(-3.2,-5.7) 11(-2.4,-5.7) 12(-1.6,-5.7) 13(-0.8,-5.7) 14(0,-5.7) 15(0.8,-5.7) 16(1.6,-5.7) 17(2.4,-5.7) 18(3.2,-5.7) 19(4,-5.7) 20(4.8,-5.7) 21(5.6,-5.7) 22(6.4,-5.7) 23(7.2,-5.7) 24(8,-5.7) 25(8.8,-5.7) 26(9.6,-5.7) 27(10.4,-5.7) 28(10.4,5.7) 29(9.6,5.7) 30(8.8,5.7) 31(8,5.7) 32(7.2,5.7) 33(6.4,5.7) 34(5.6,5.7) 35(4.8,5.7) 36(4,5.7) 37(3.2,5.7) 38(2.4,5.7) 39(1.6,5.7) 40(0.8,5.7) 41(0,5.7) 42(-0.8,5.7) 43(-1.6,5.7) 44(-2.4,5.7) 45(-3.2,5.7) 46(-4,5.7) 47(-4.8,5.7) 48(-5.6,5.7) 49(-6.4,5.7) 50(-7.2,5.7) 51(-8,5.7) 52(-8.8,5.7) 53(-9.6,5.7) 54(-10.4,5.7)
  silkscreen extent -11.33,-5.67 11.15,4.4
